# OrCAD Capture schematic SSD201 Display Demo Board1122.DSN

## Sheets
1 011.RMII: size B; title: SSD201 Display Demo Board; rev: r01; company: SigmaStar; note: RMII
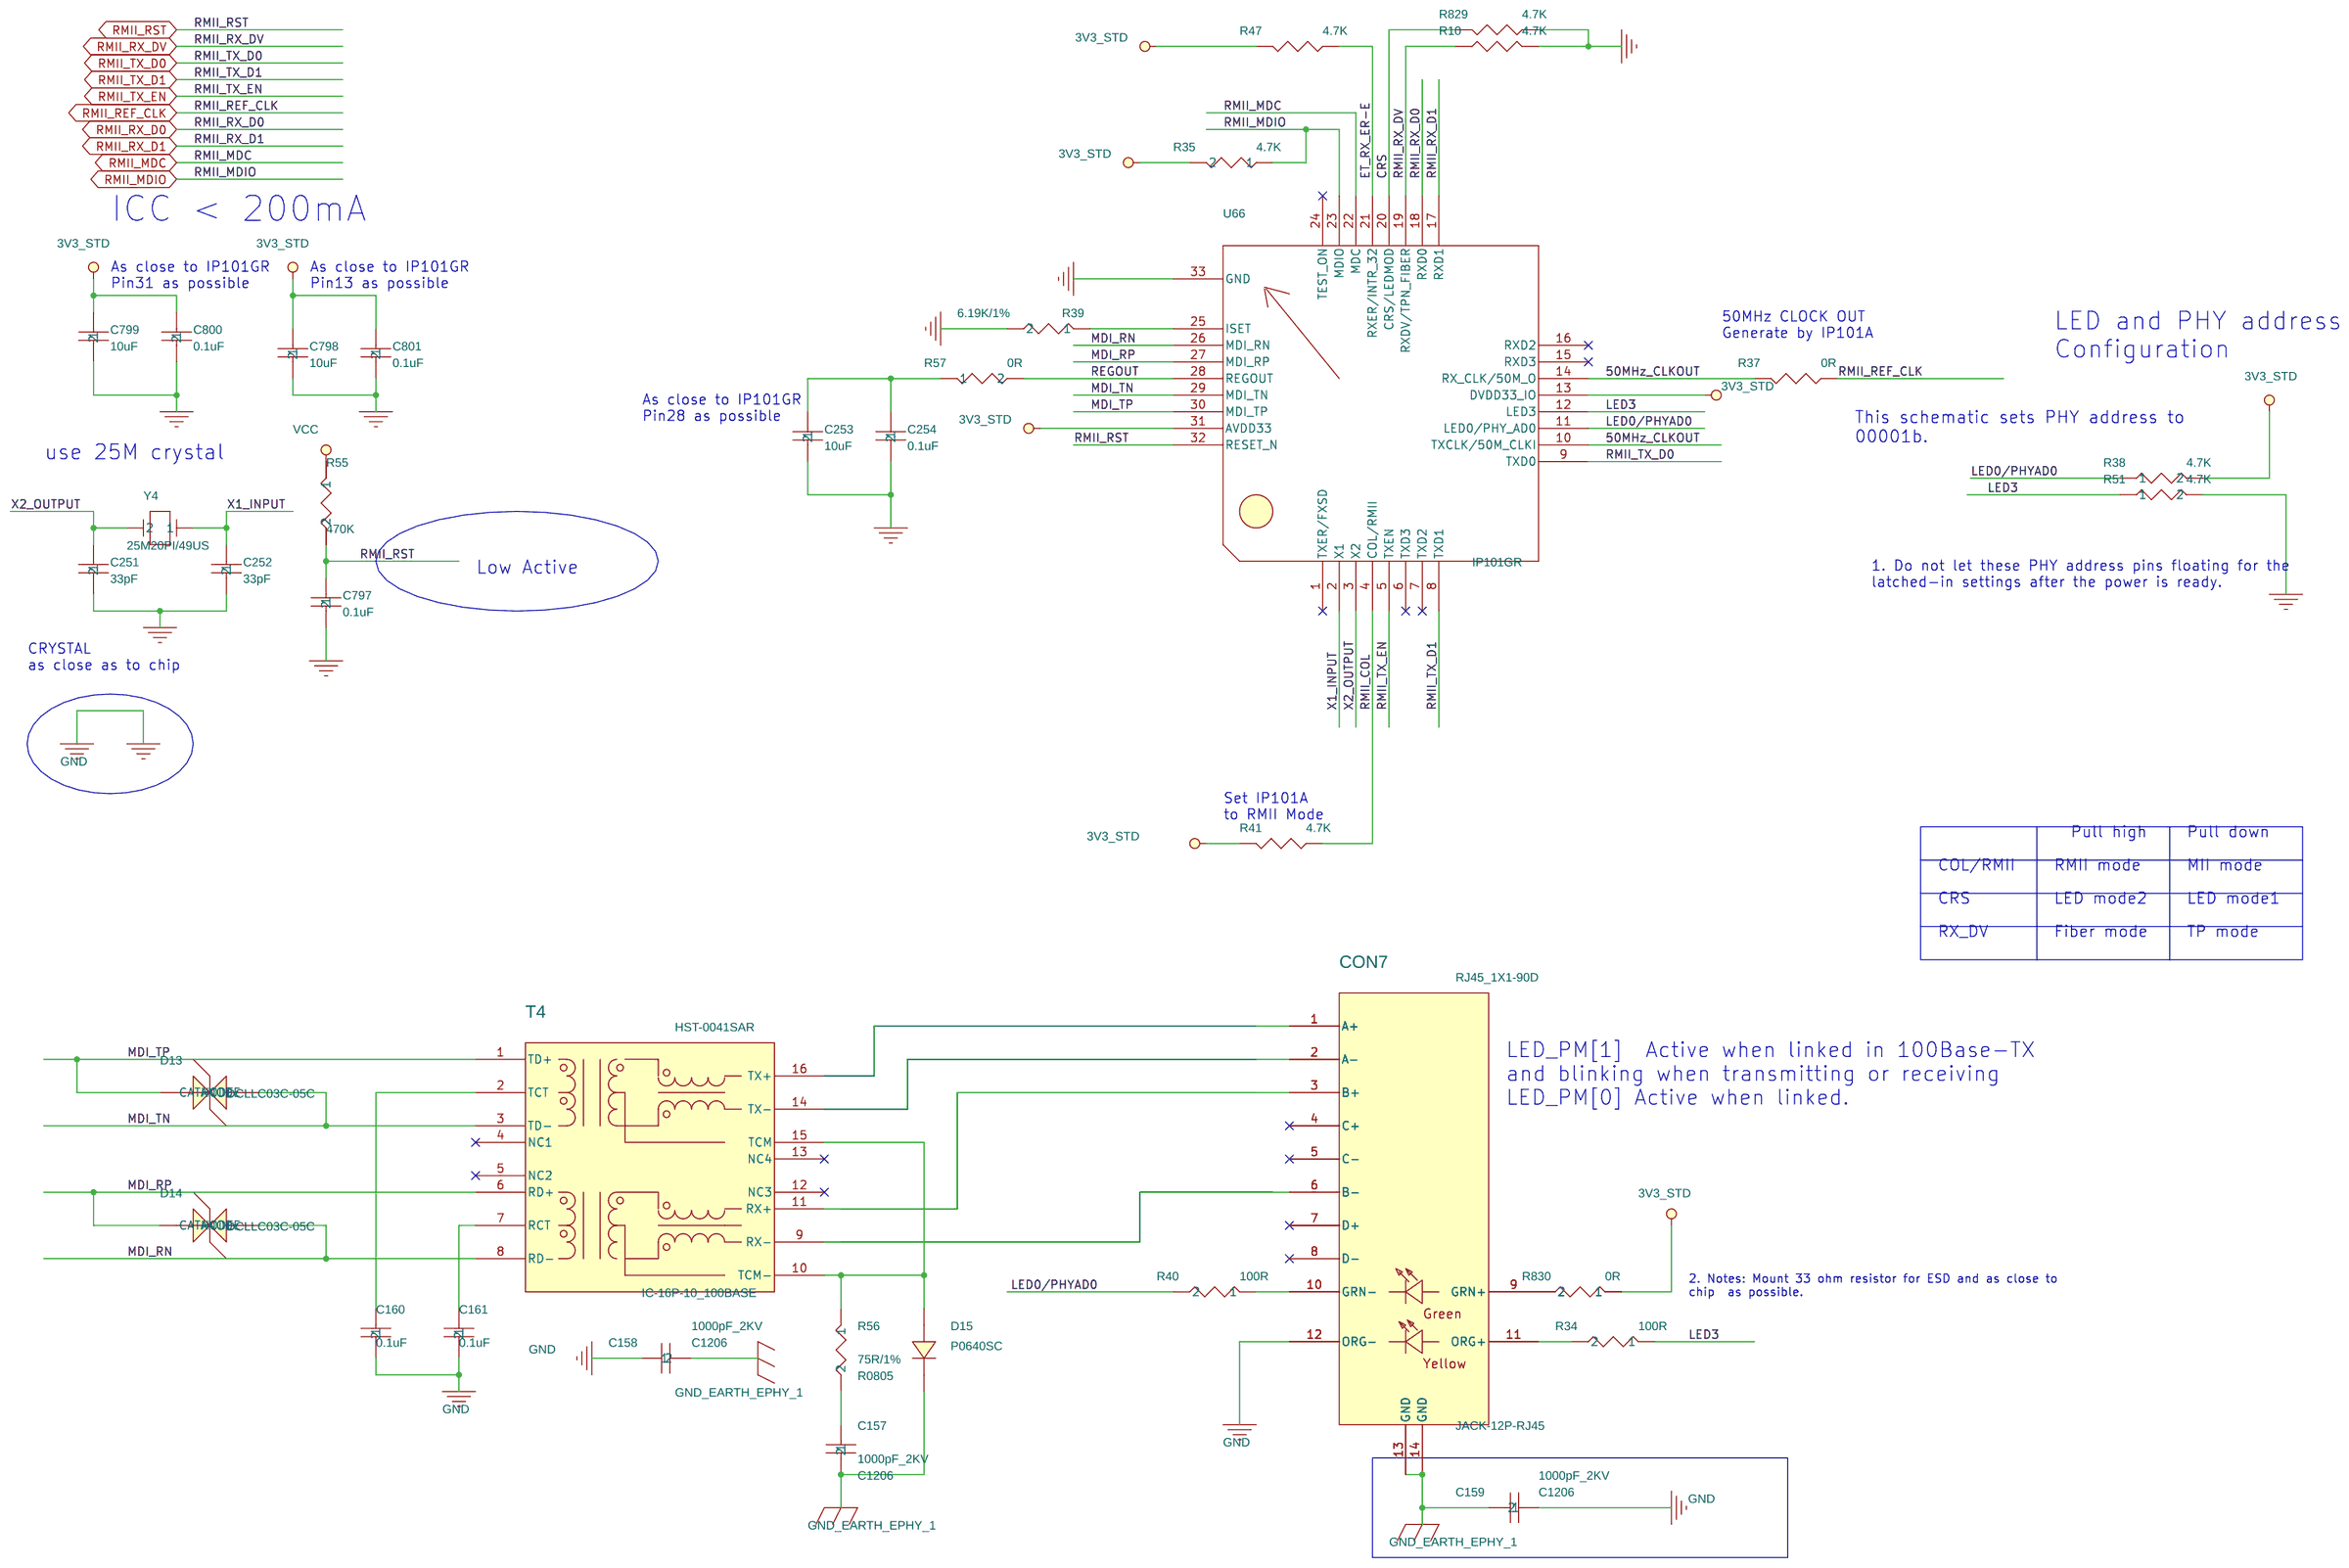
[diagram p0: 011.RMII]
2 001. Revision: rev: r0.1; note: Revision History
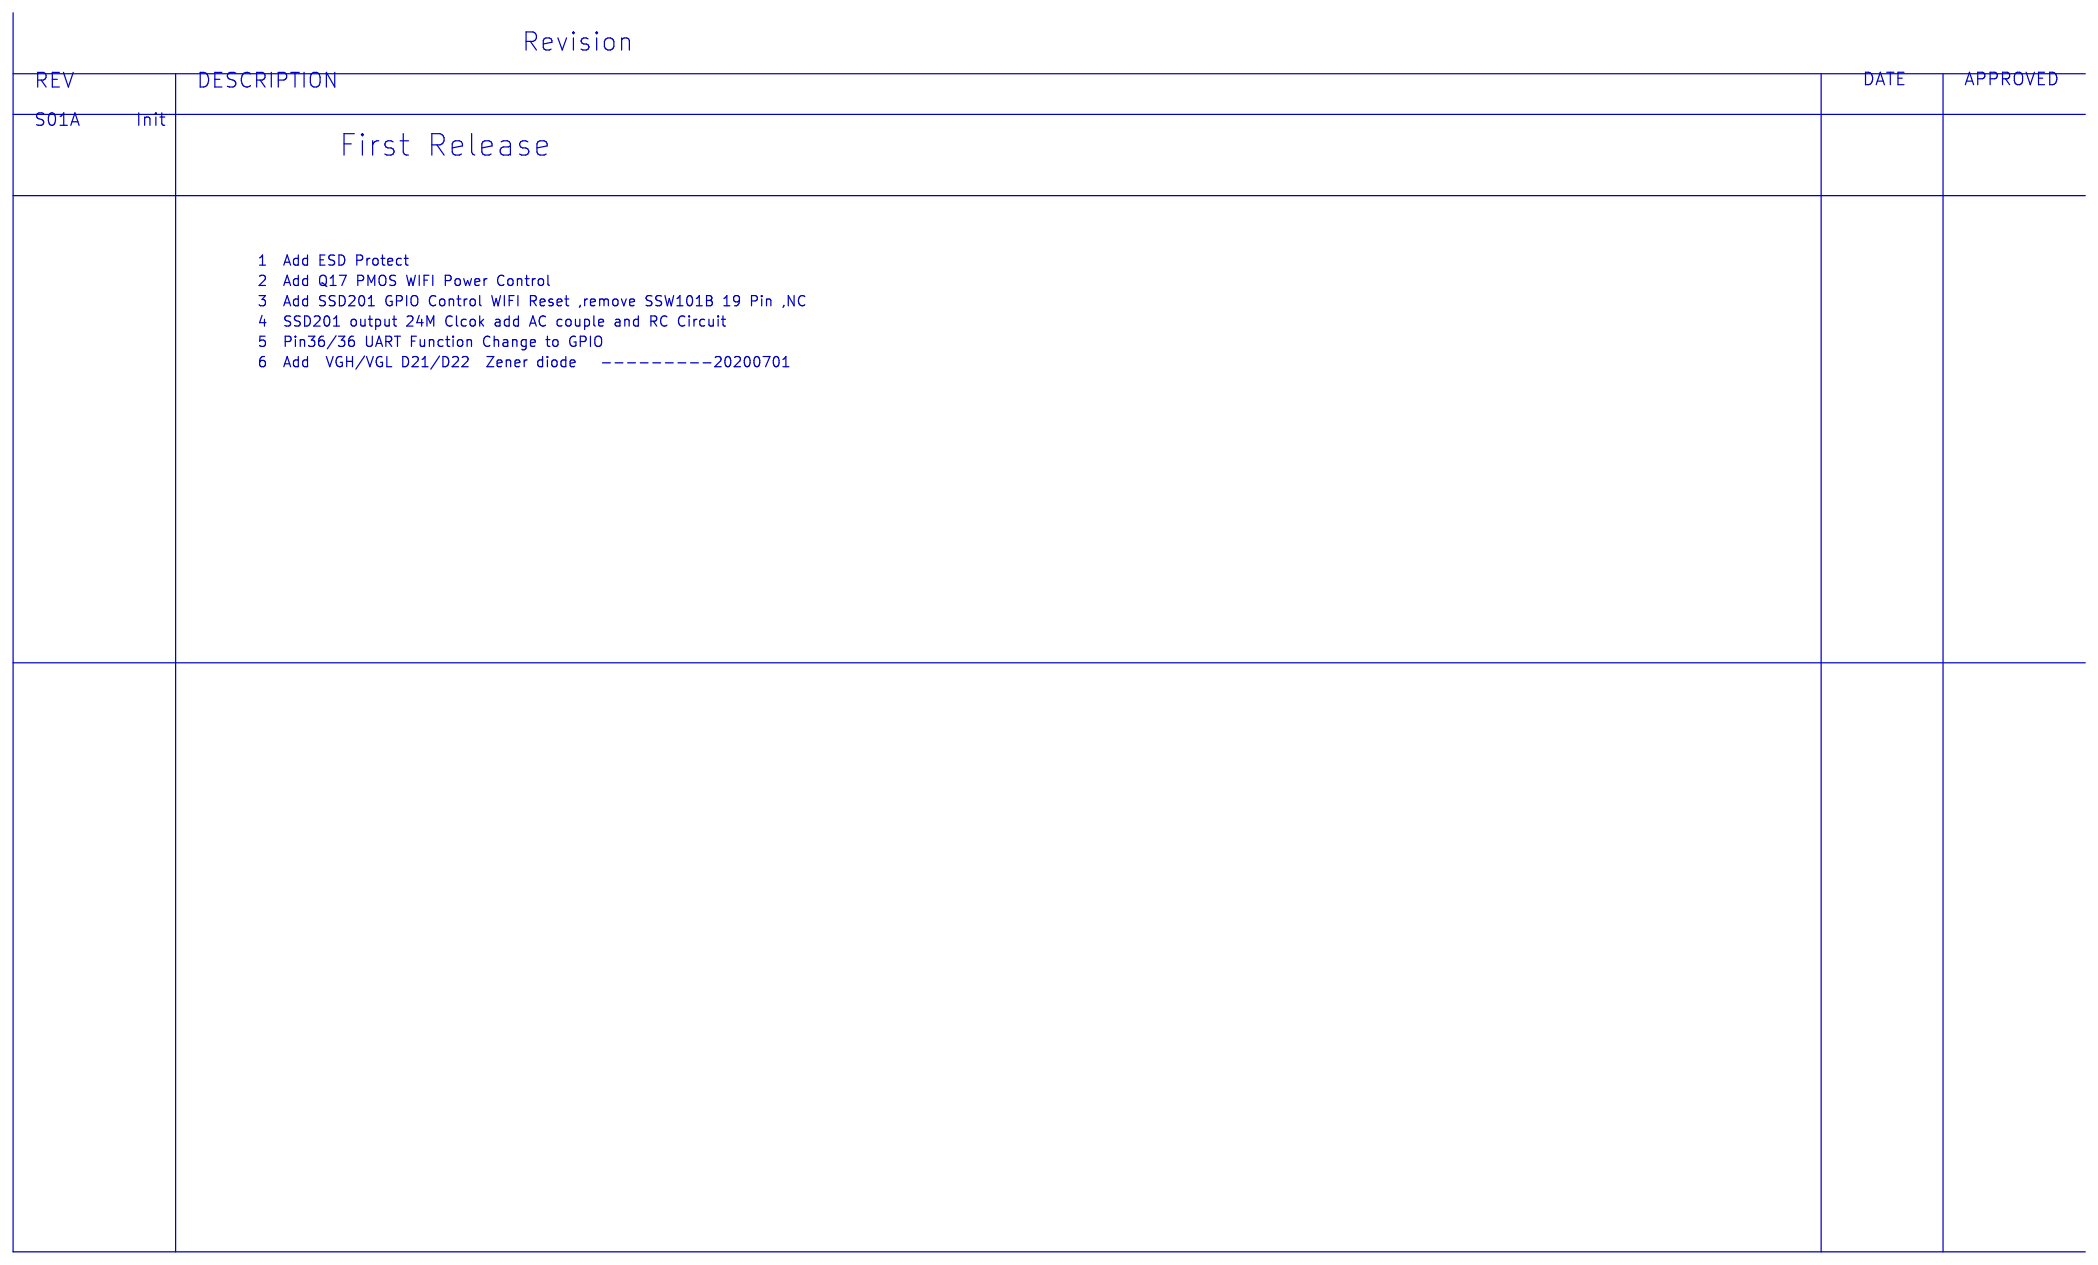
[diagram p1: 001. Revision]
3 002. Block Diagrom: rev: r0.1; note: Block Diagram
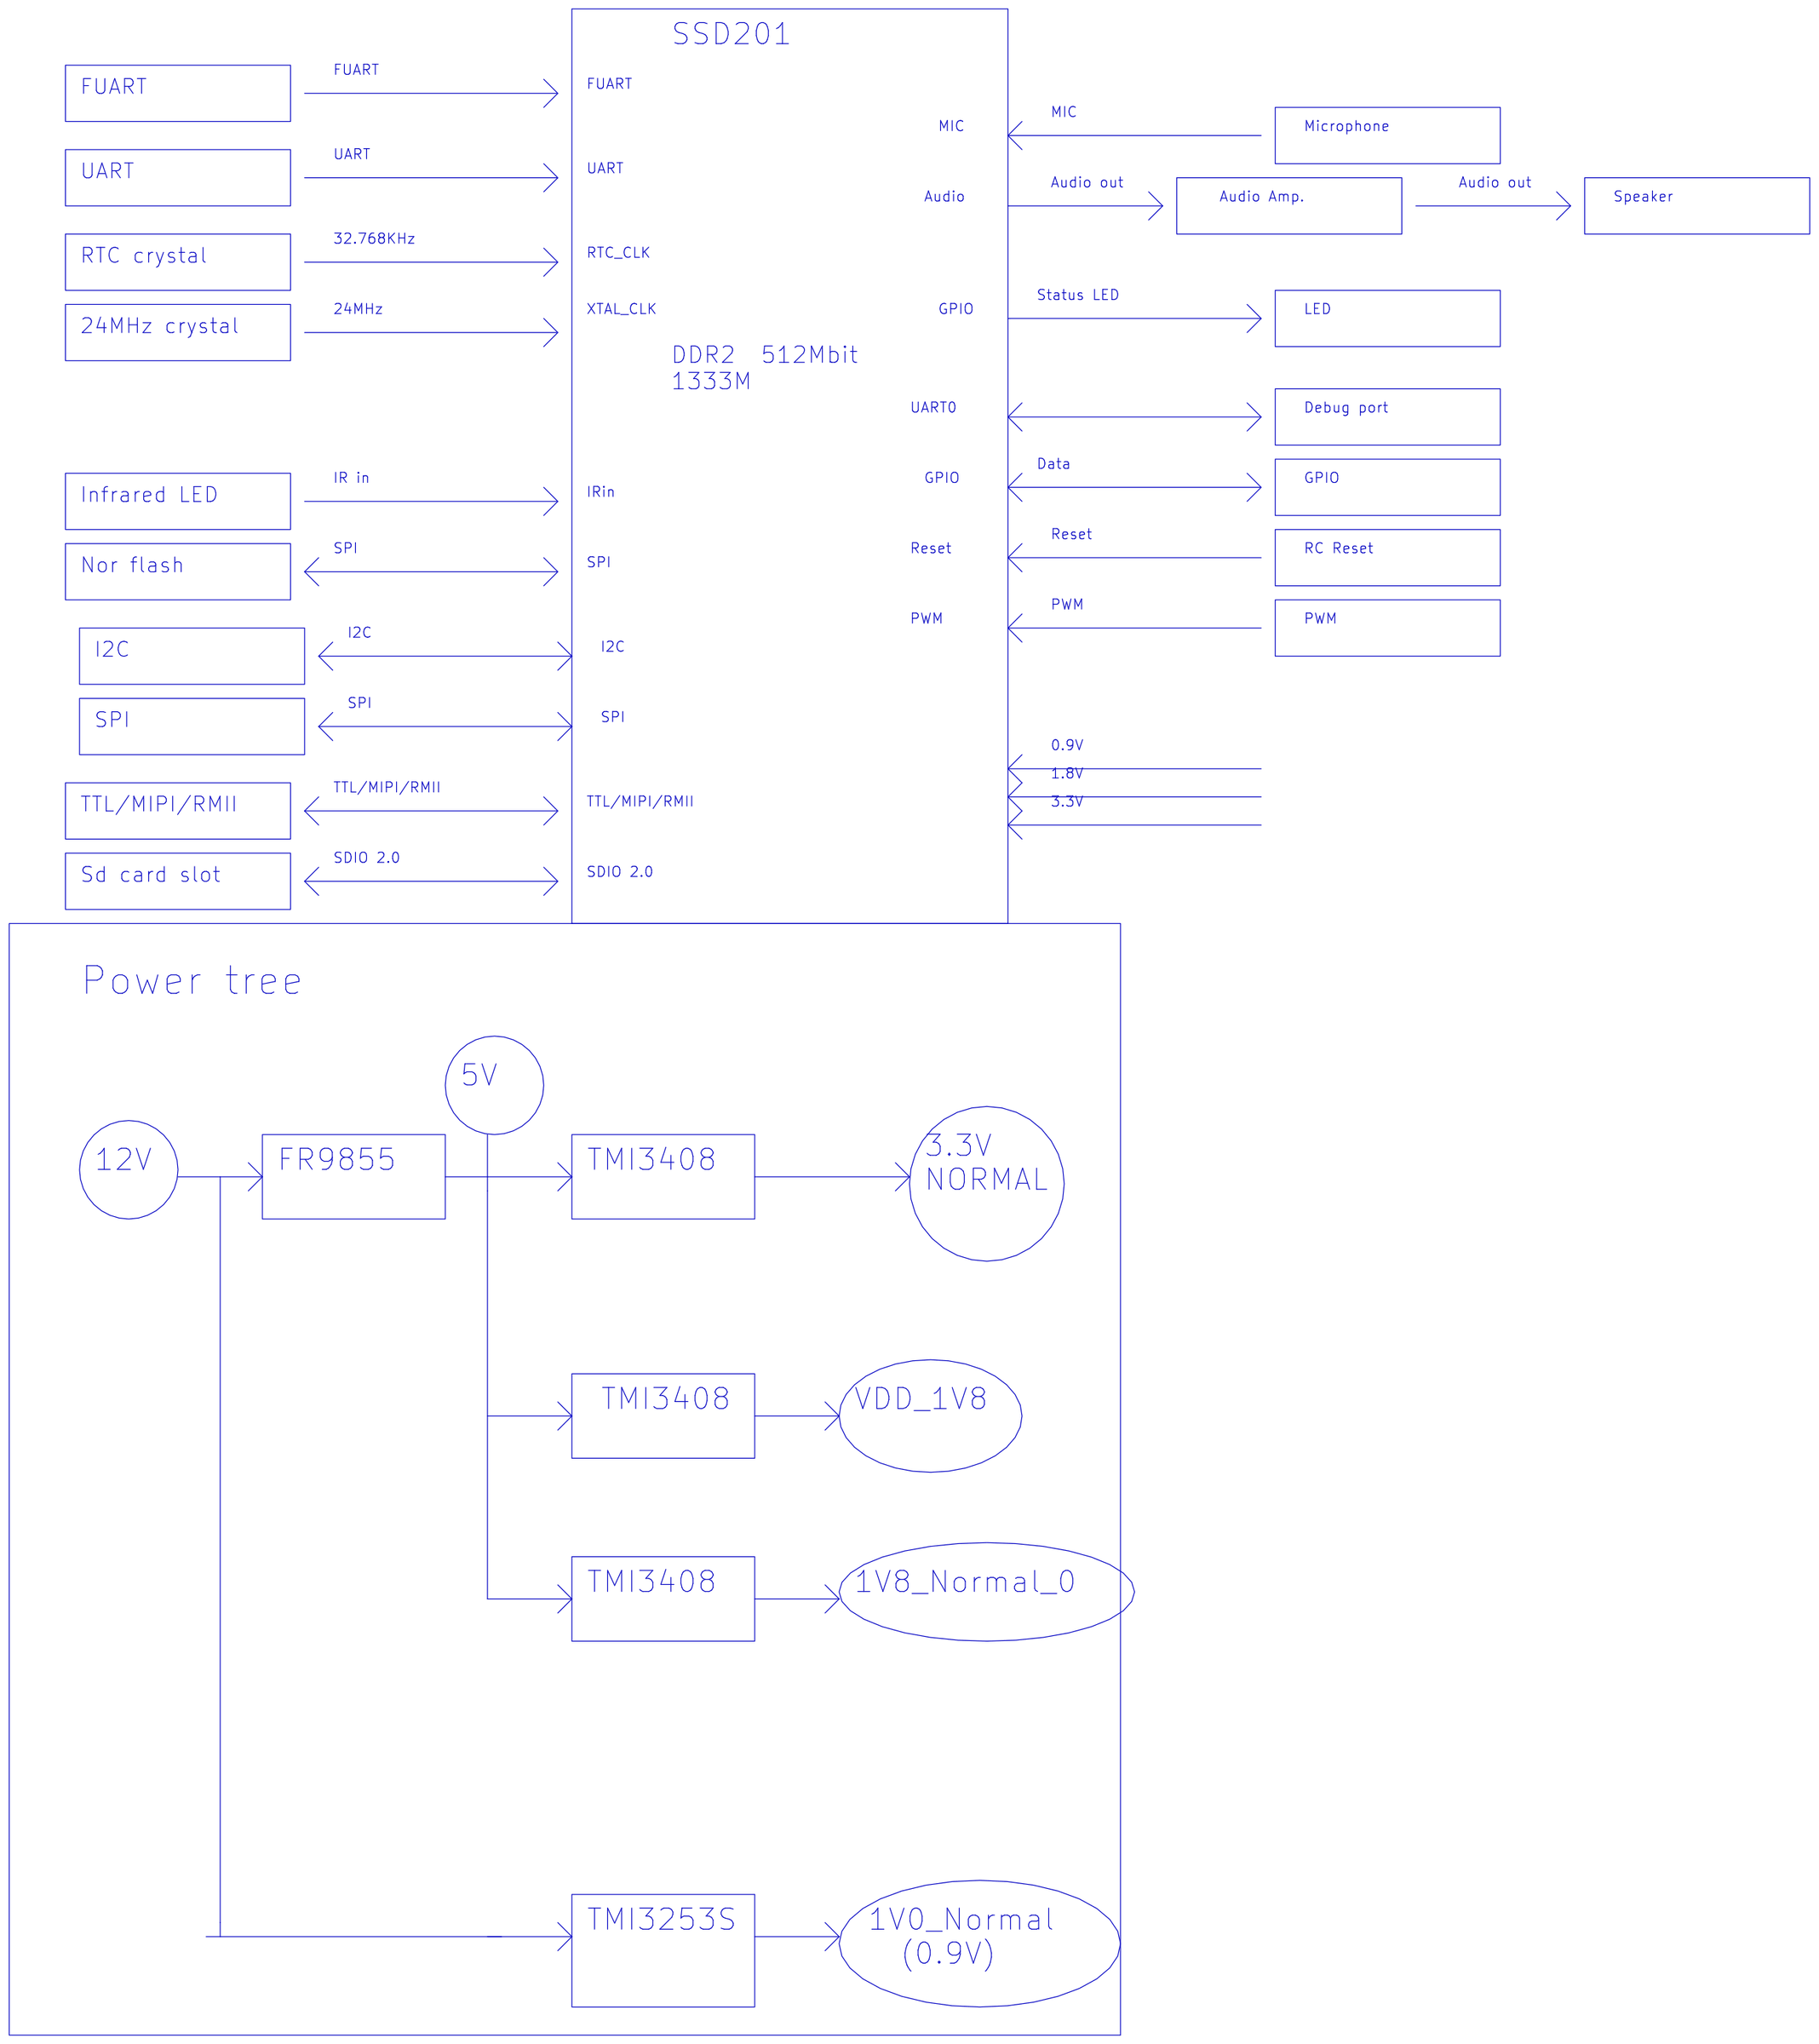
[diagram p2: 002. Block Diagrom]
4 003. Power: size C; rev: r0.1; note: Power
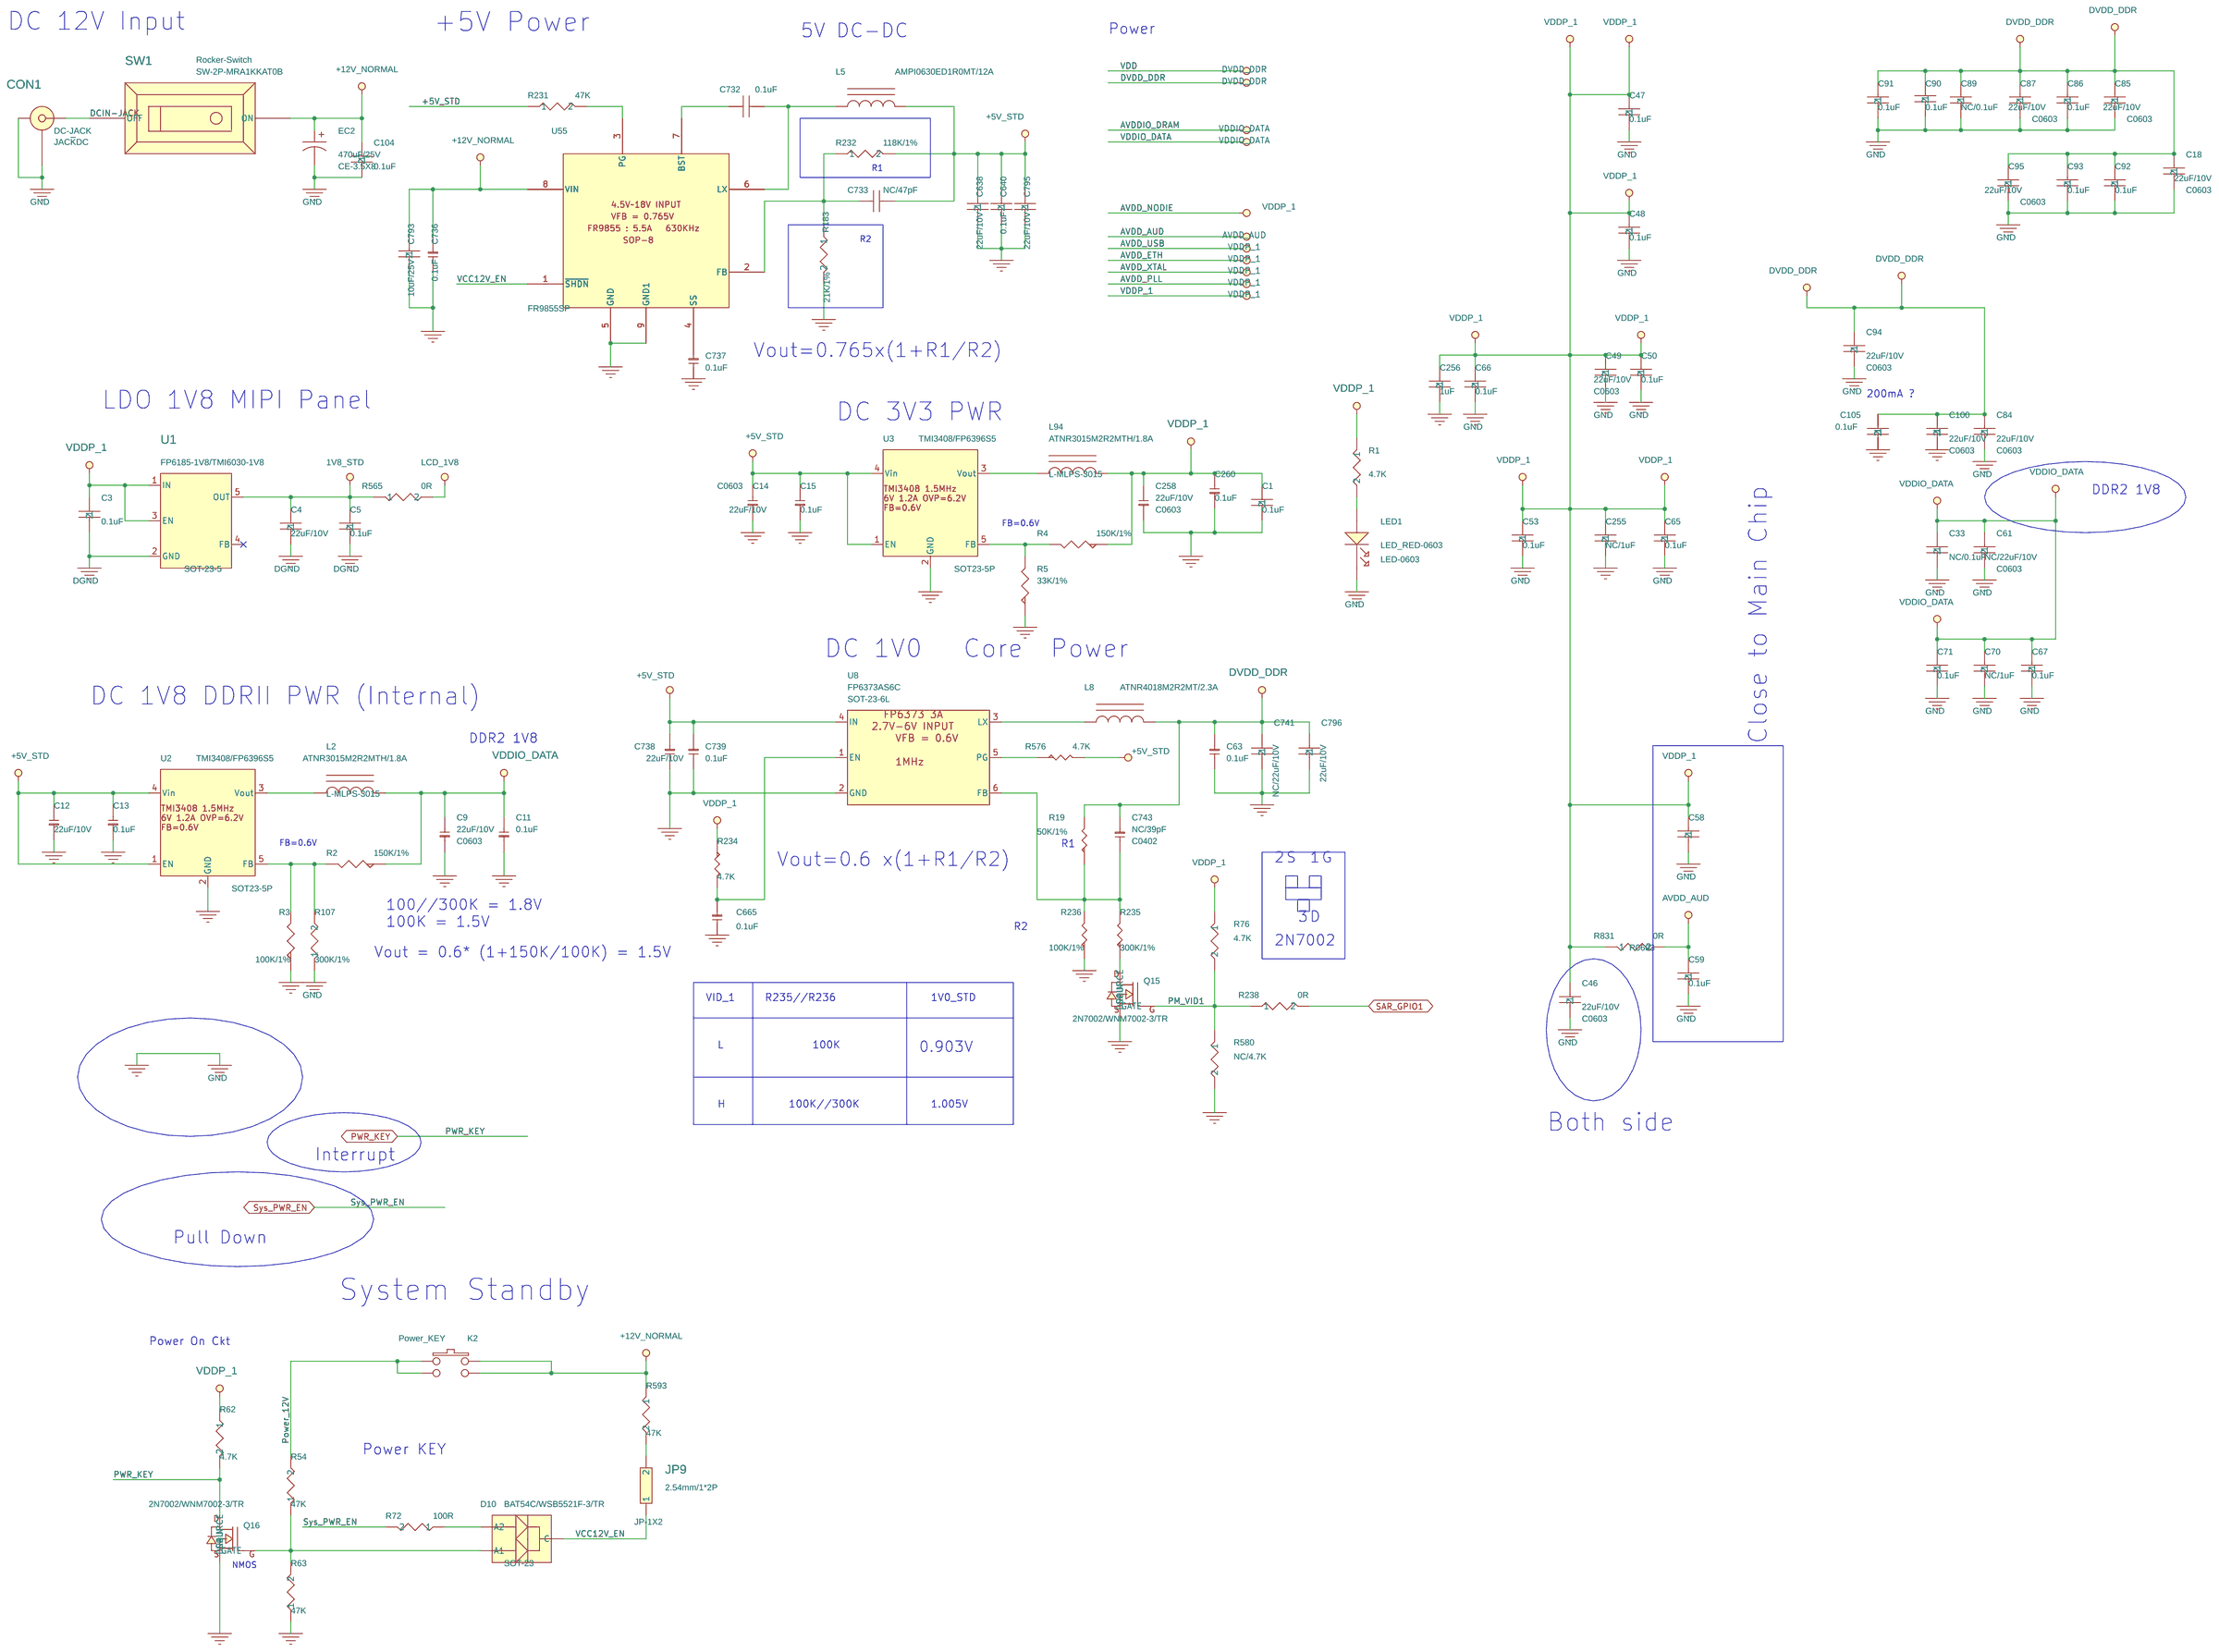
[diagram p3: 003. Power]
5 004. SSD201: size C; rev: r0.1; note: SOC_ SPI Flash / JTAG / IR / eFuse
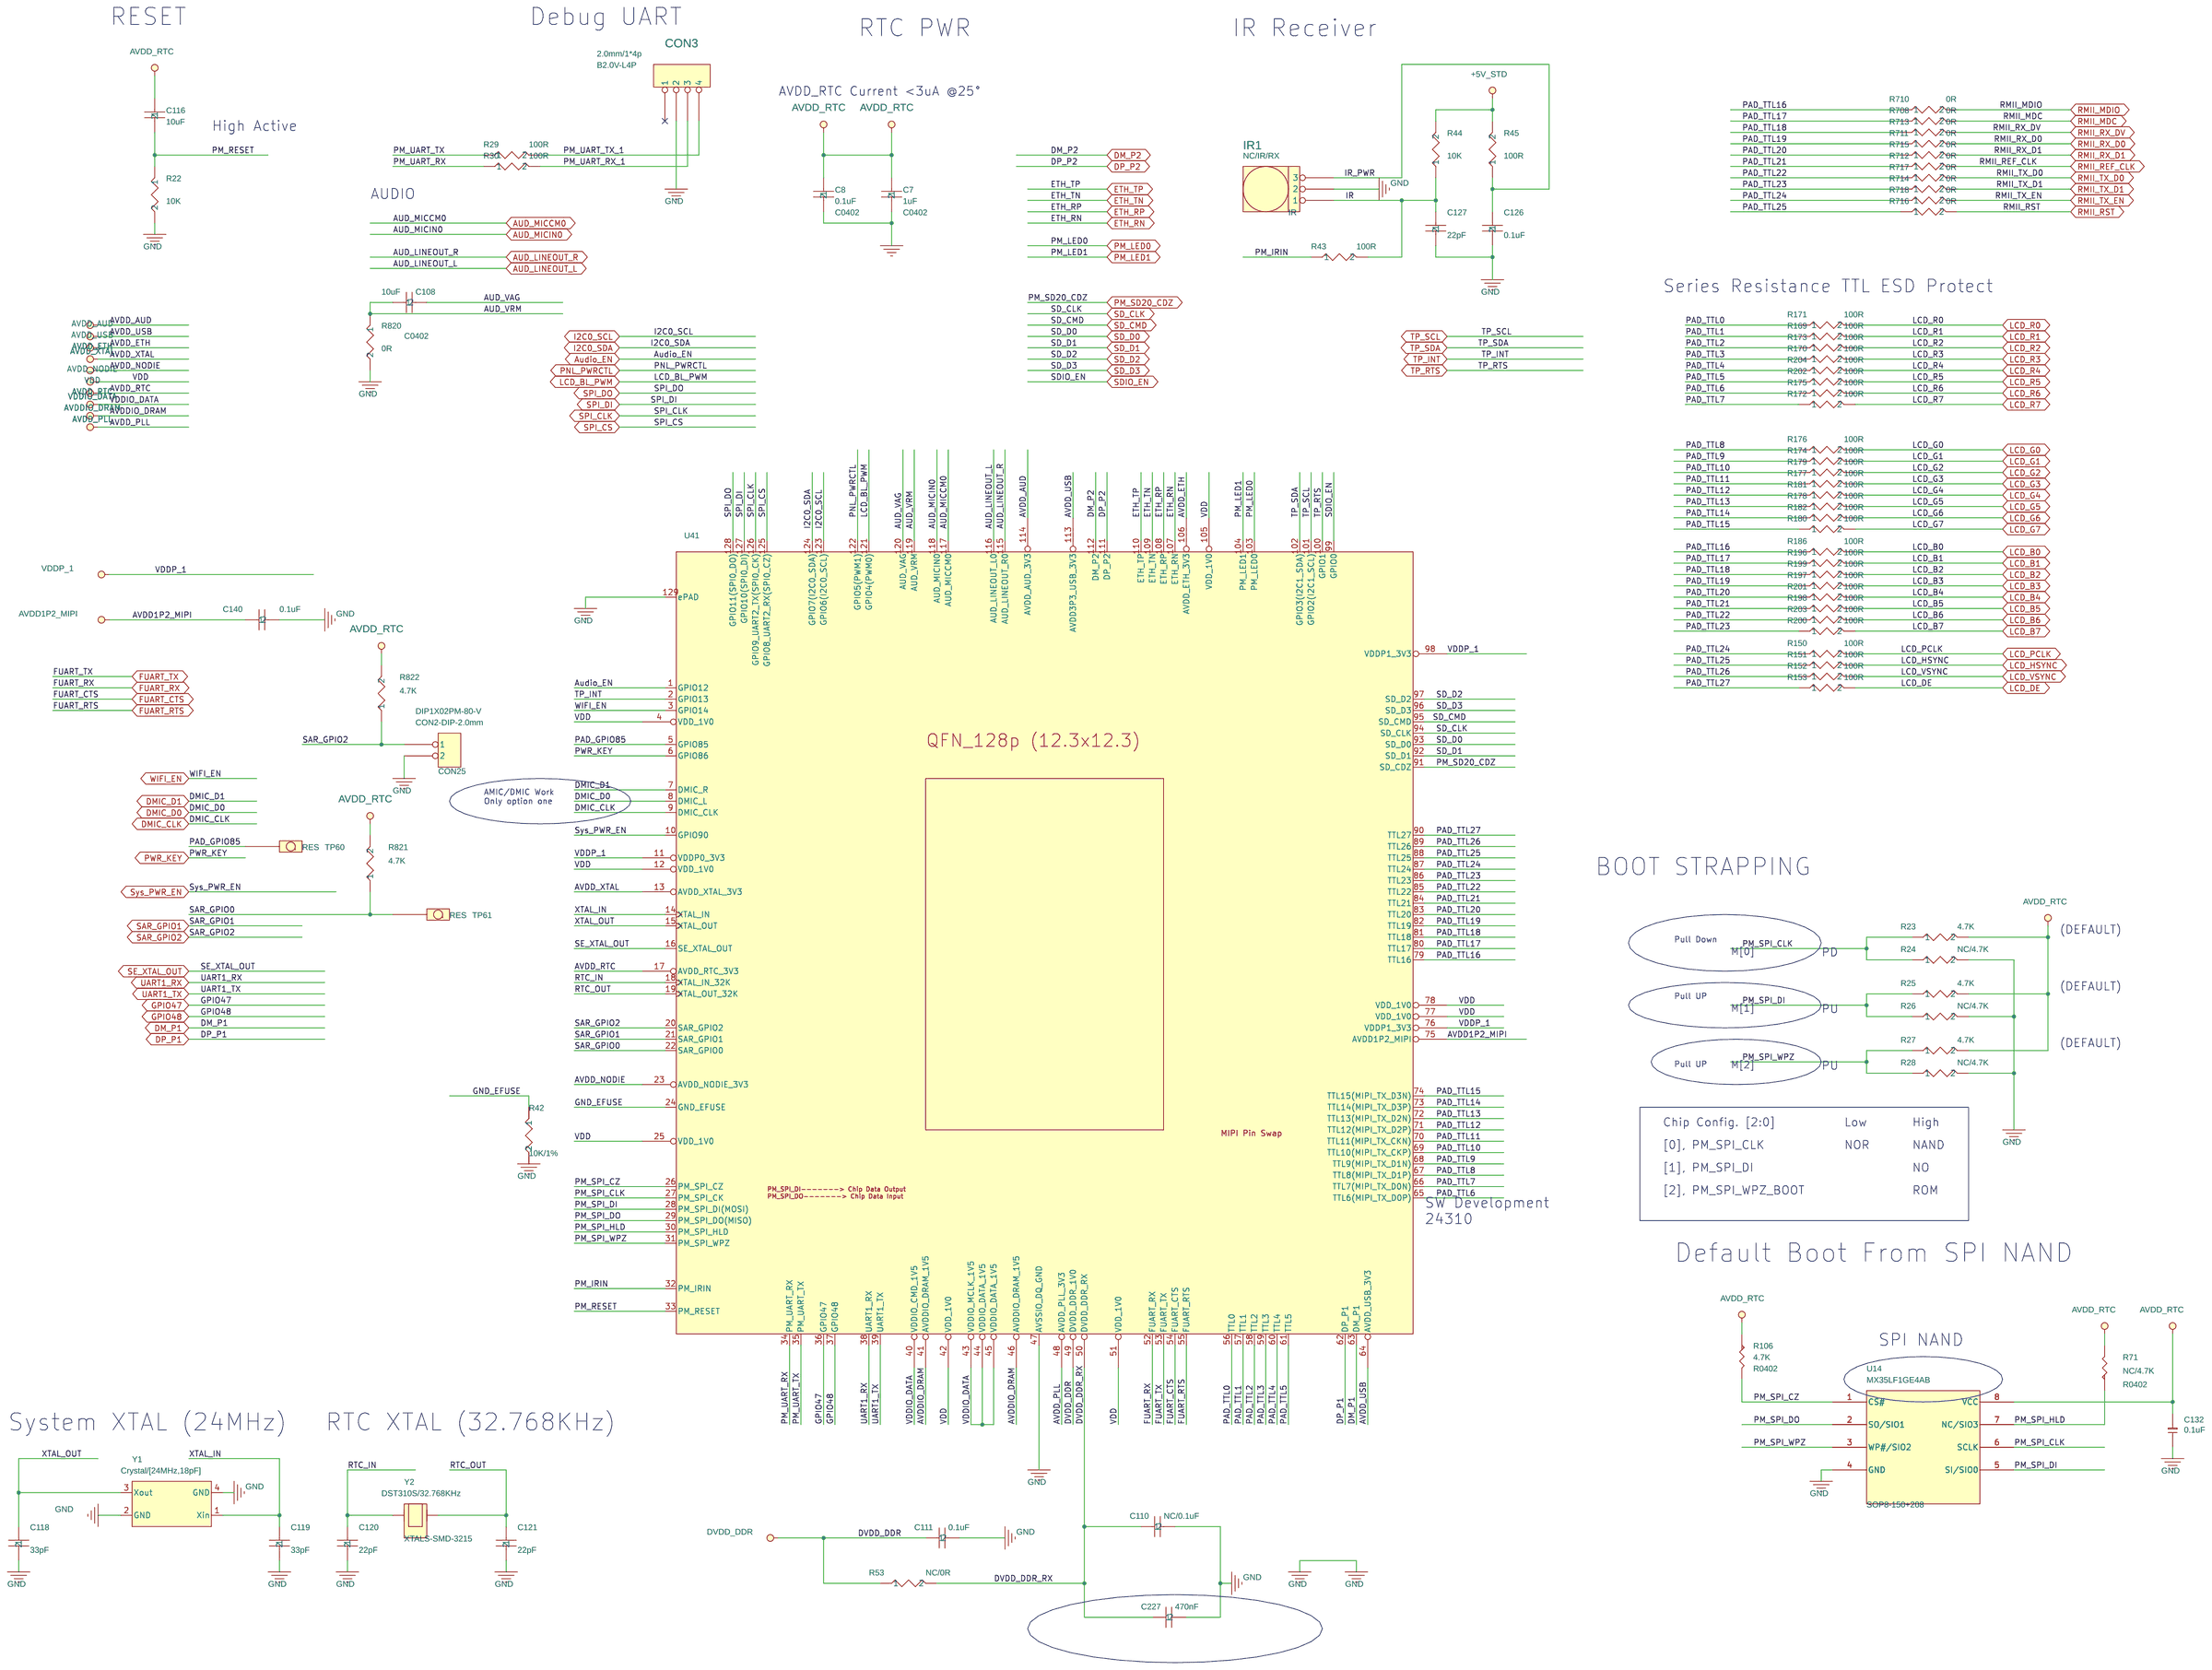
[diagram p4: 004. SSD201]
6 008. Audio: size A; note: Audio
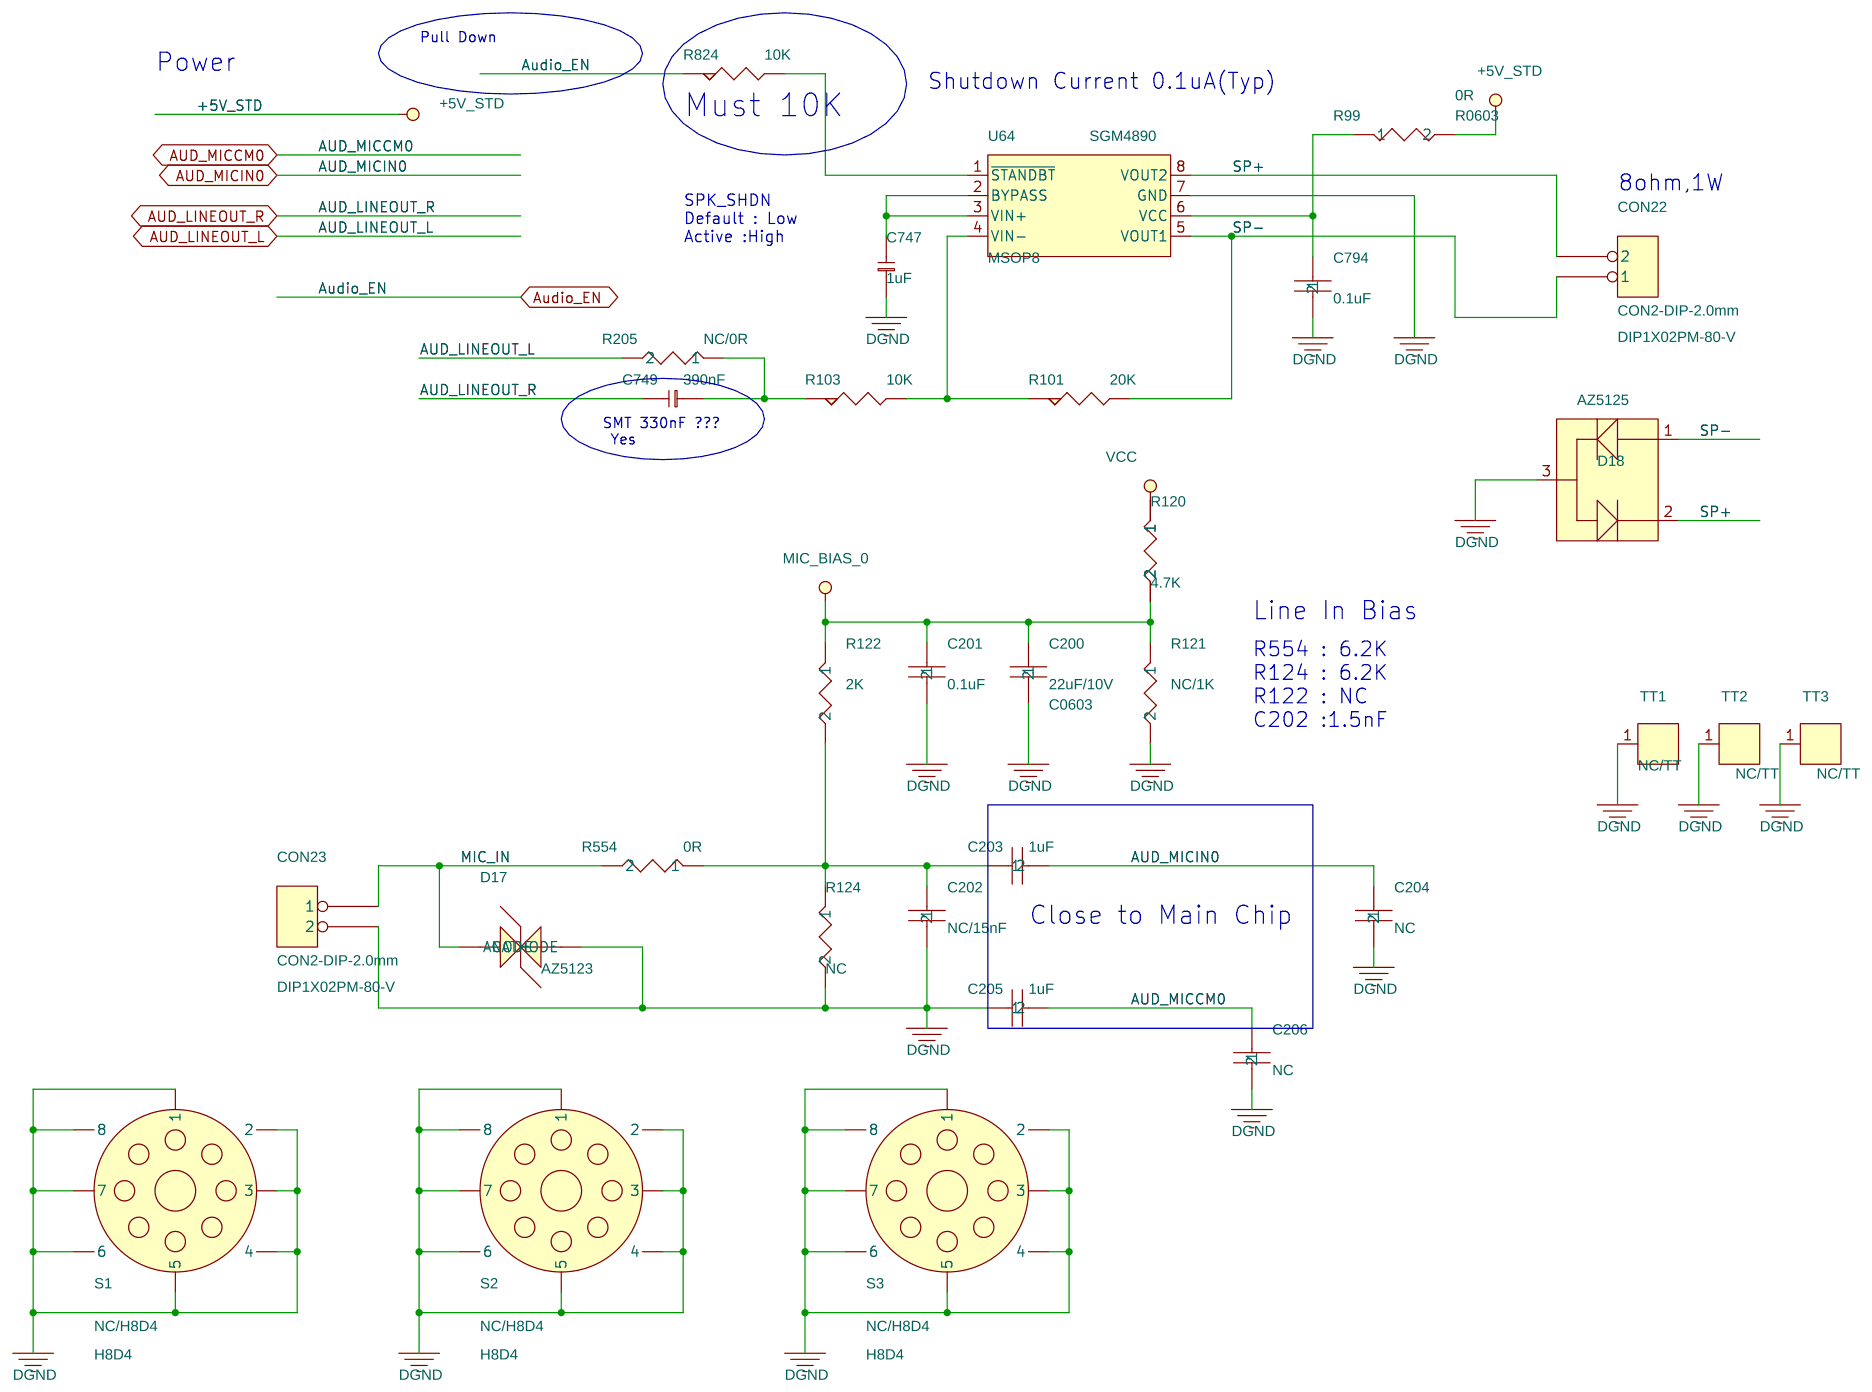
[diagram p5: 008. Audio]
7 009.TTL Panel: size B; note: Display-TTL Panel
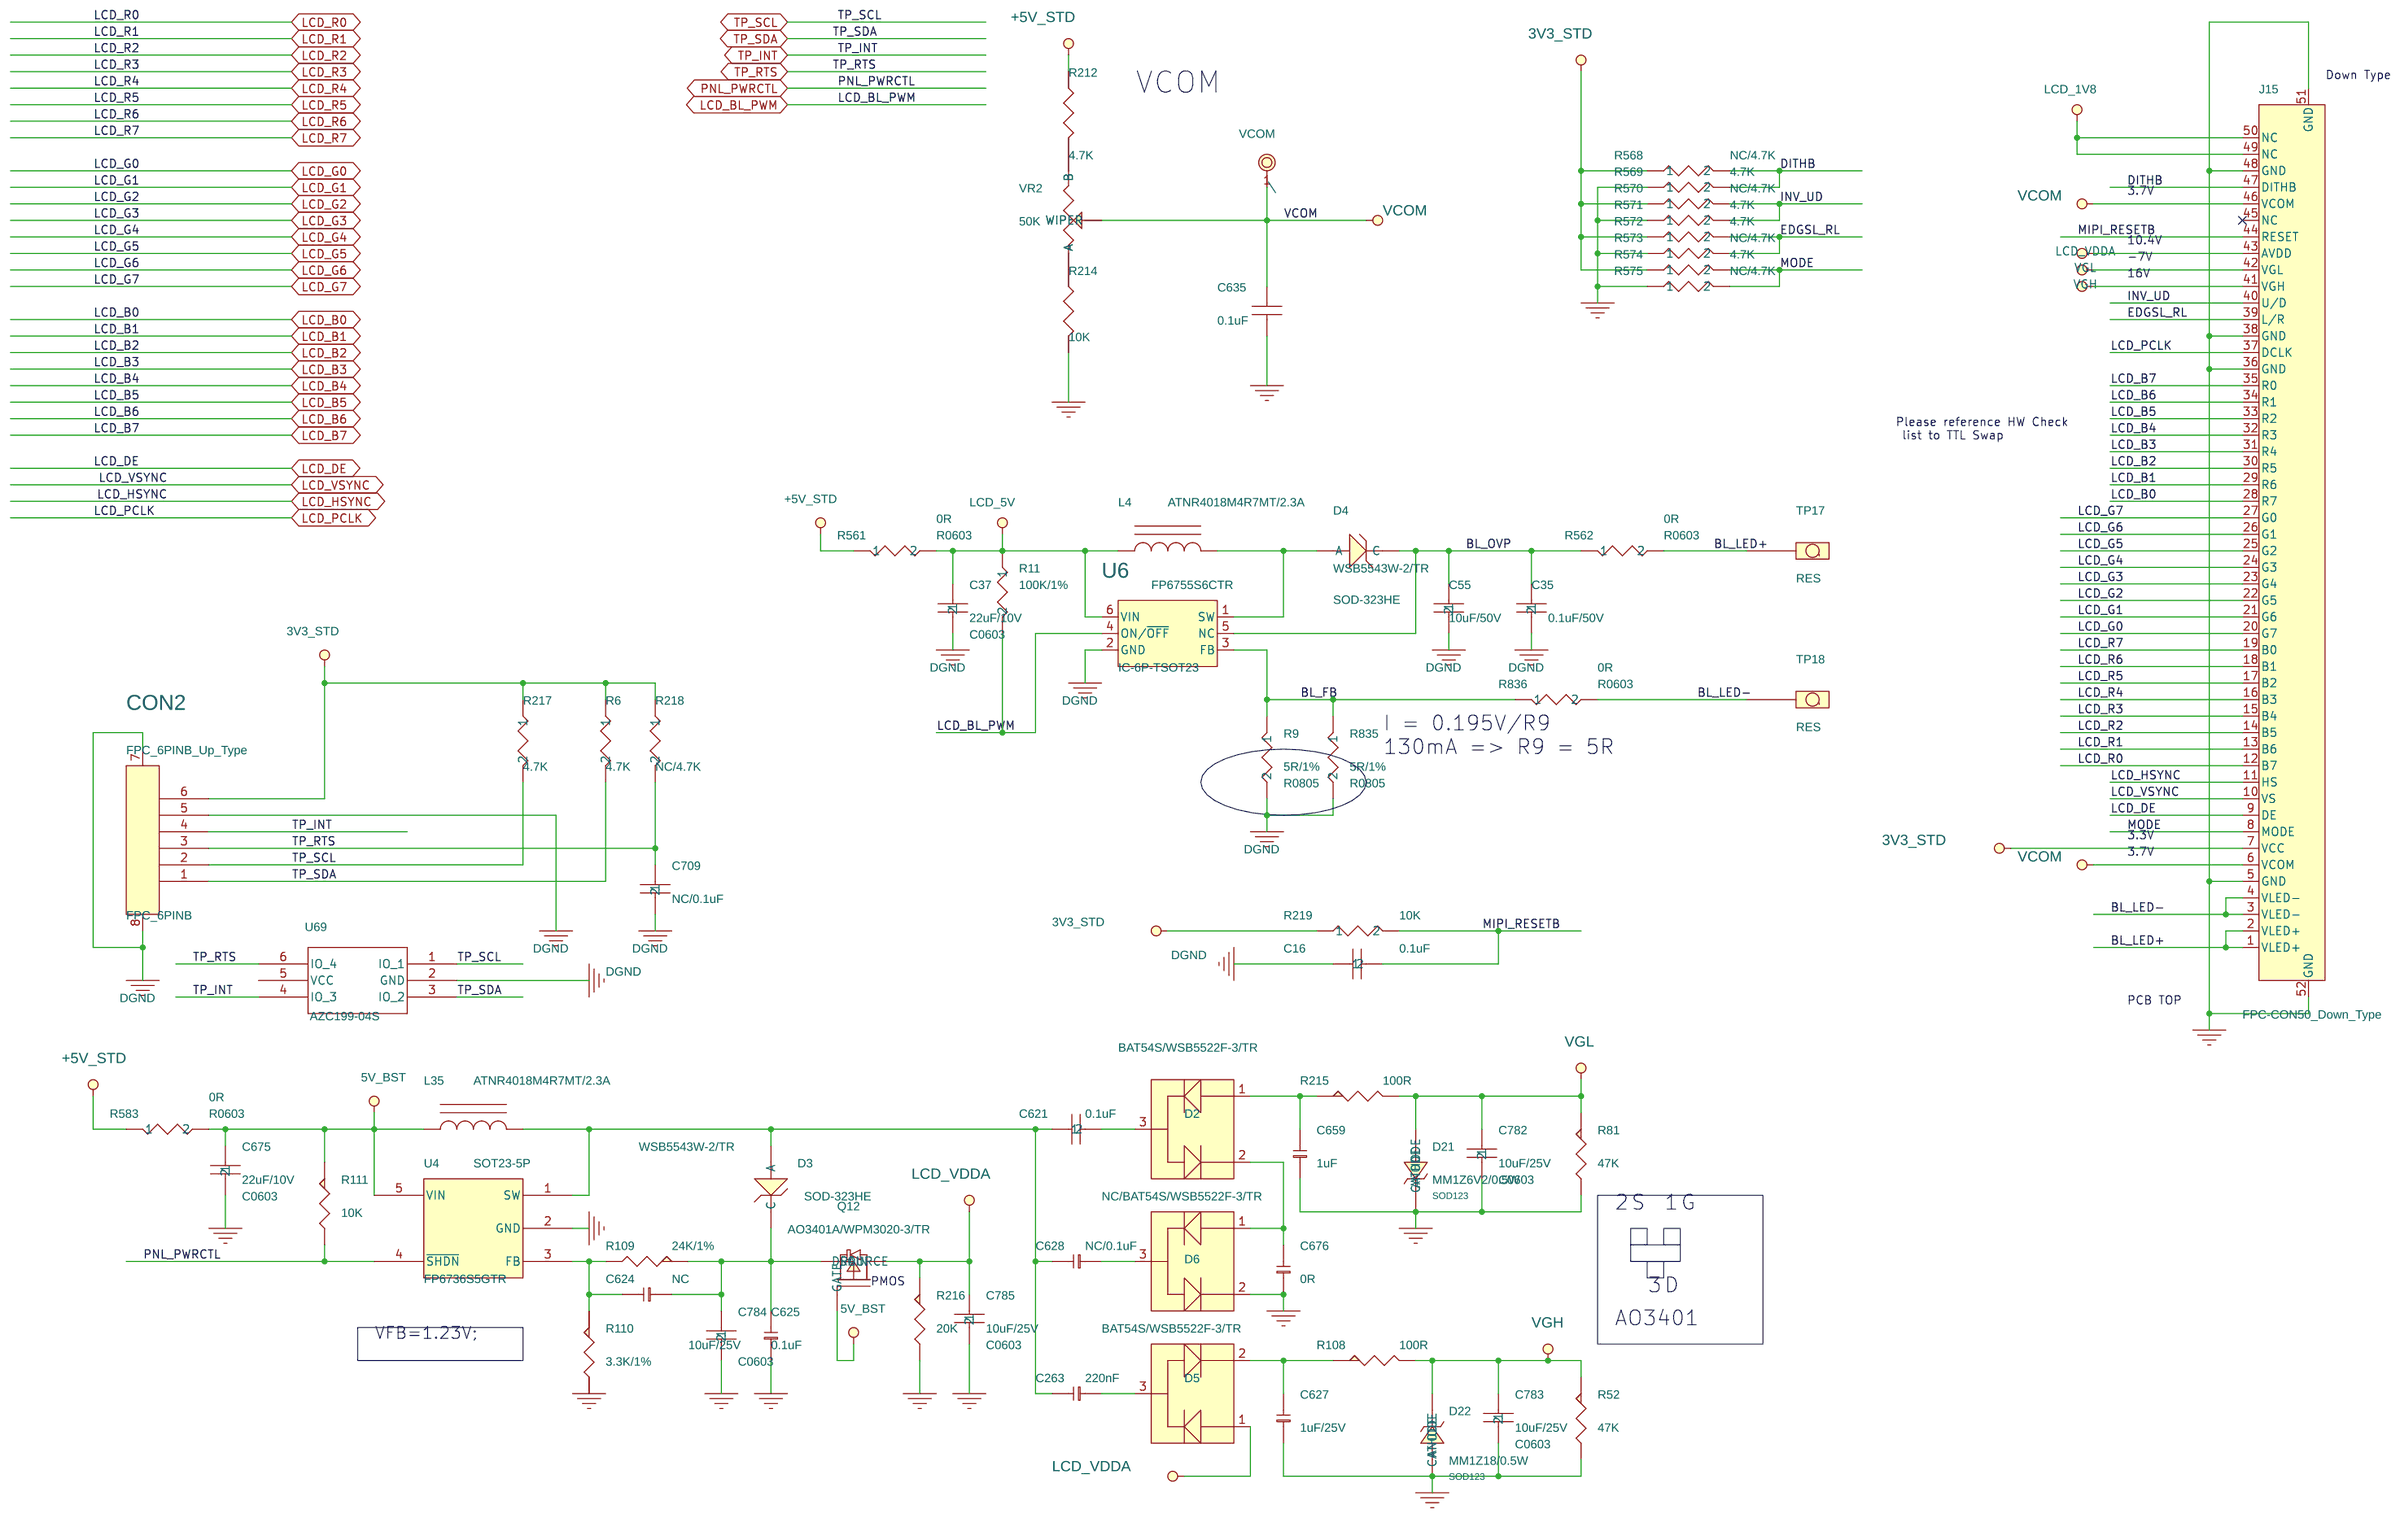
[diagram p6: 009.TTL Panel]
8 010.USB_WIFI: size B; note: USB WIFI
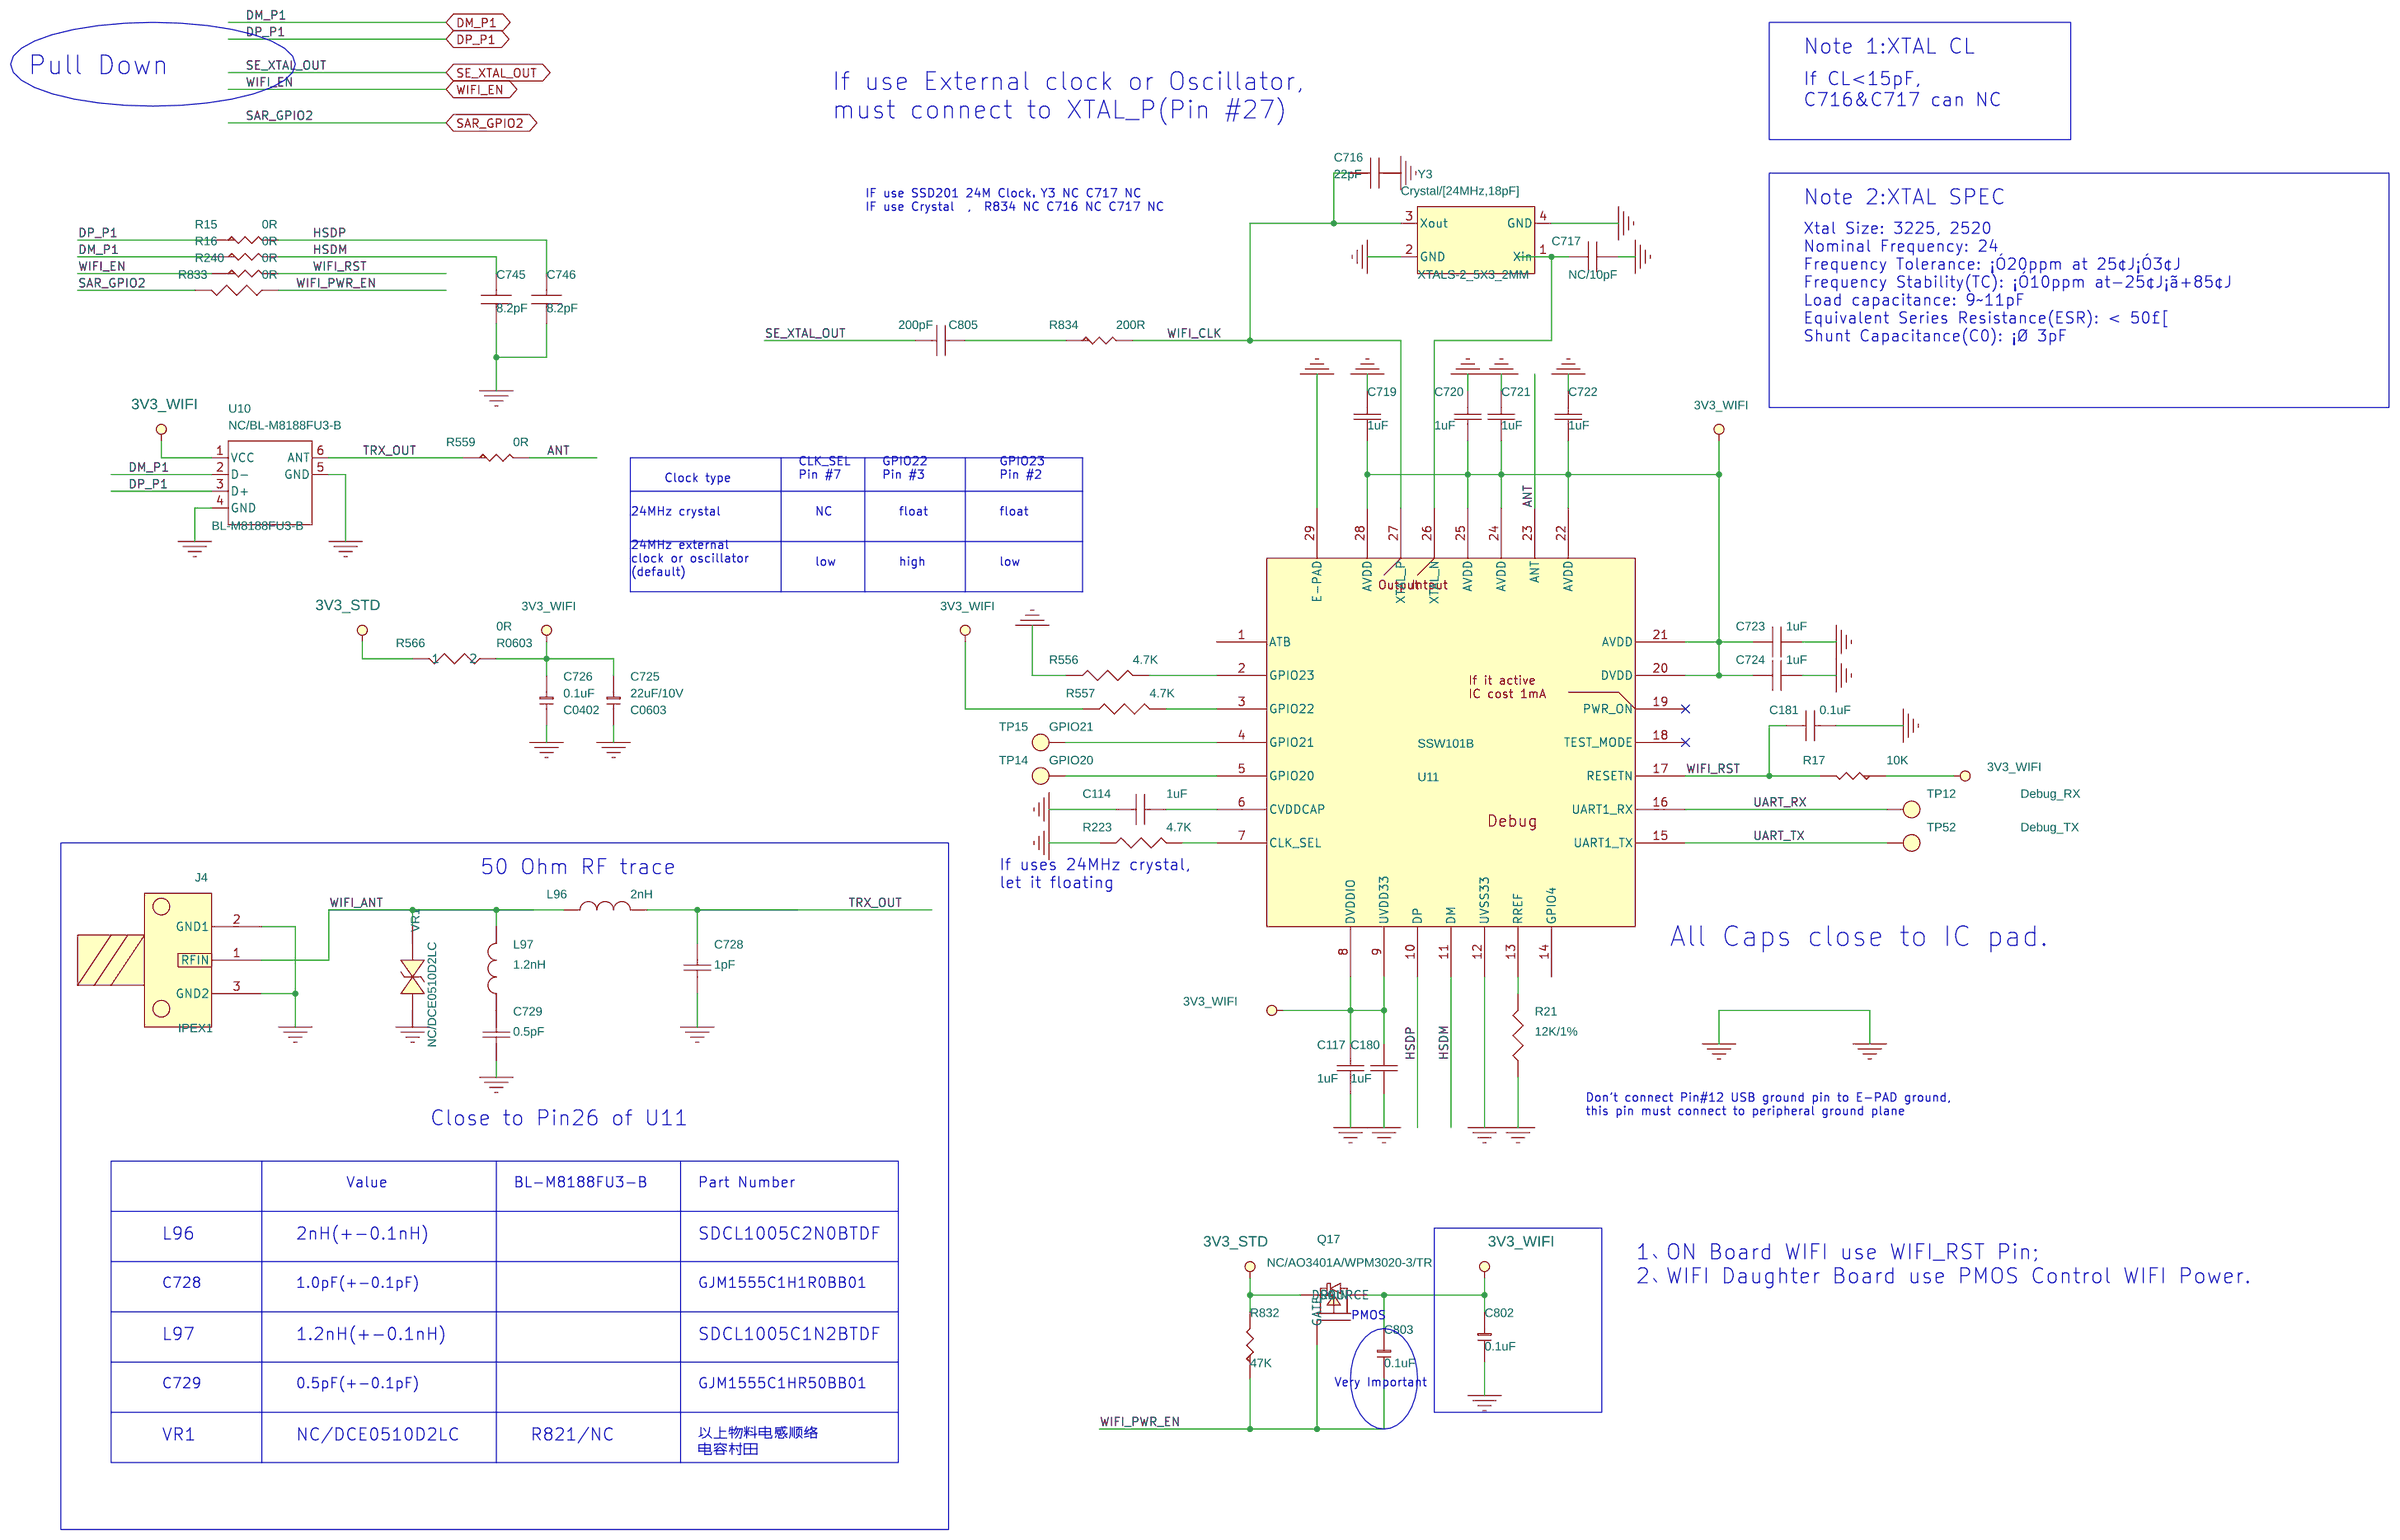
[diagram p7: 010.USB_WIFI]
9 007.SD/SDIO: size A; note: SD
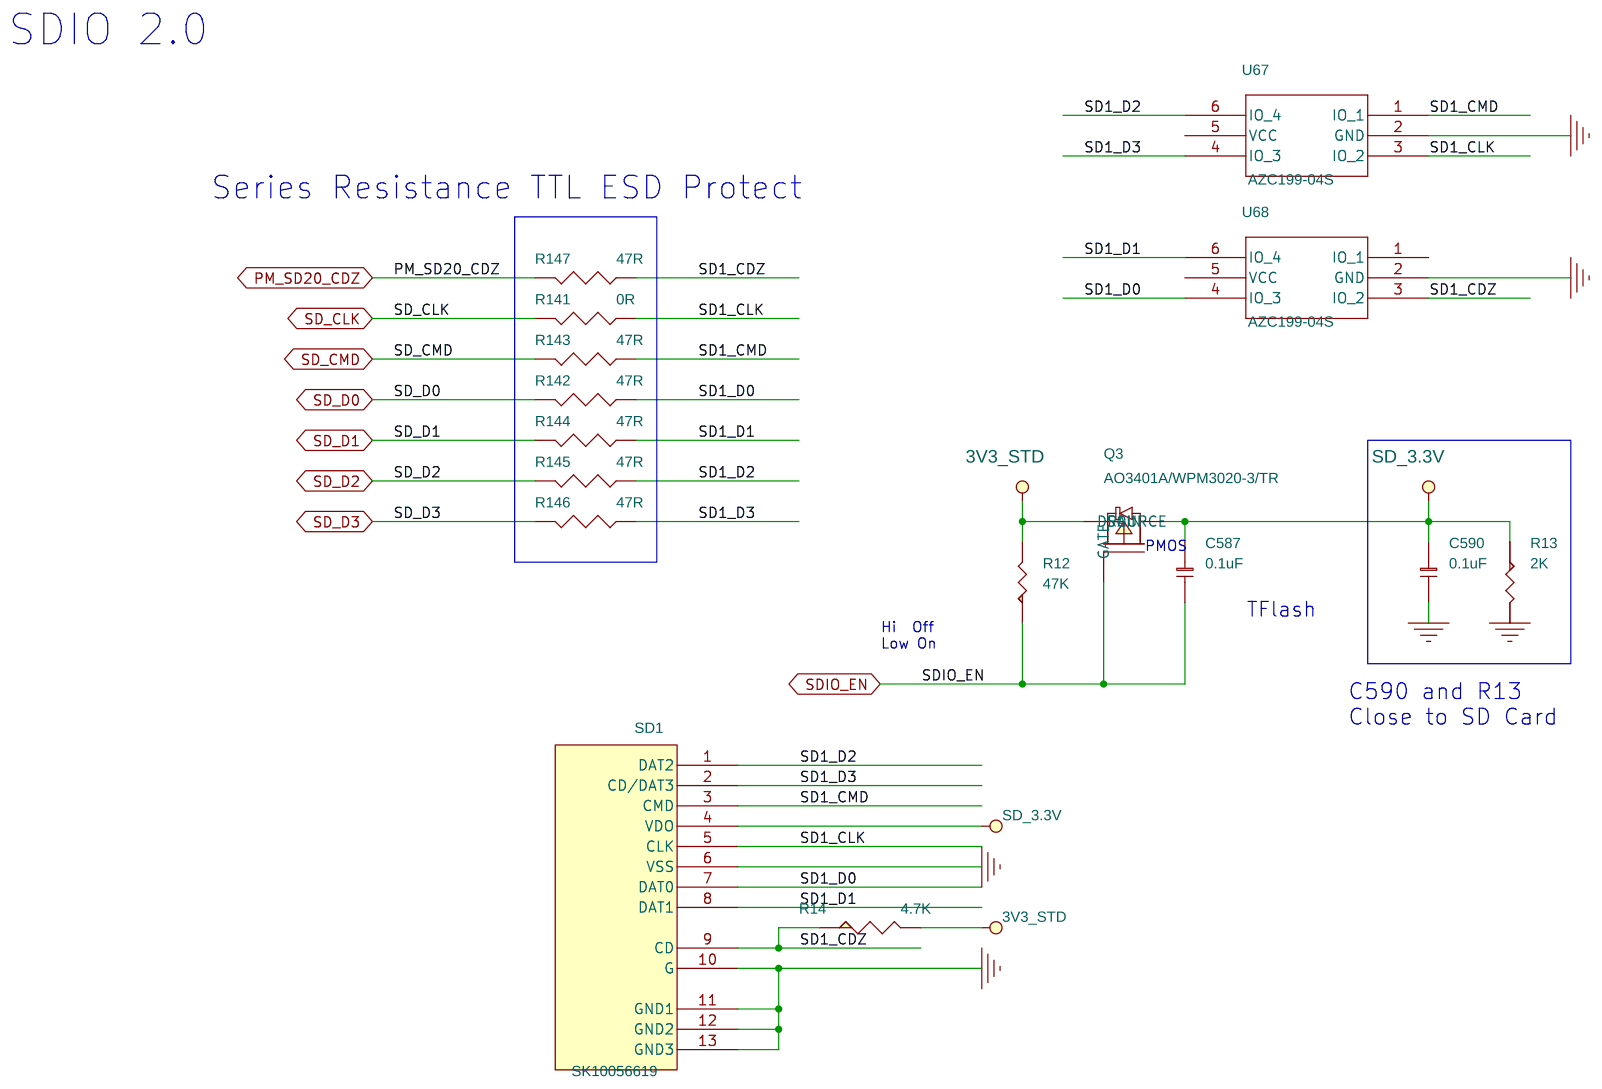
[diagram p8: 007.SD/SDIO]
10 006. USB/ePHY: size B; note: USB
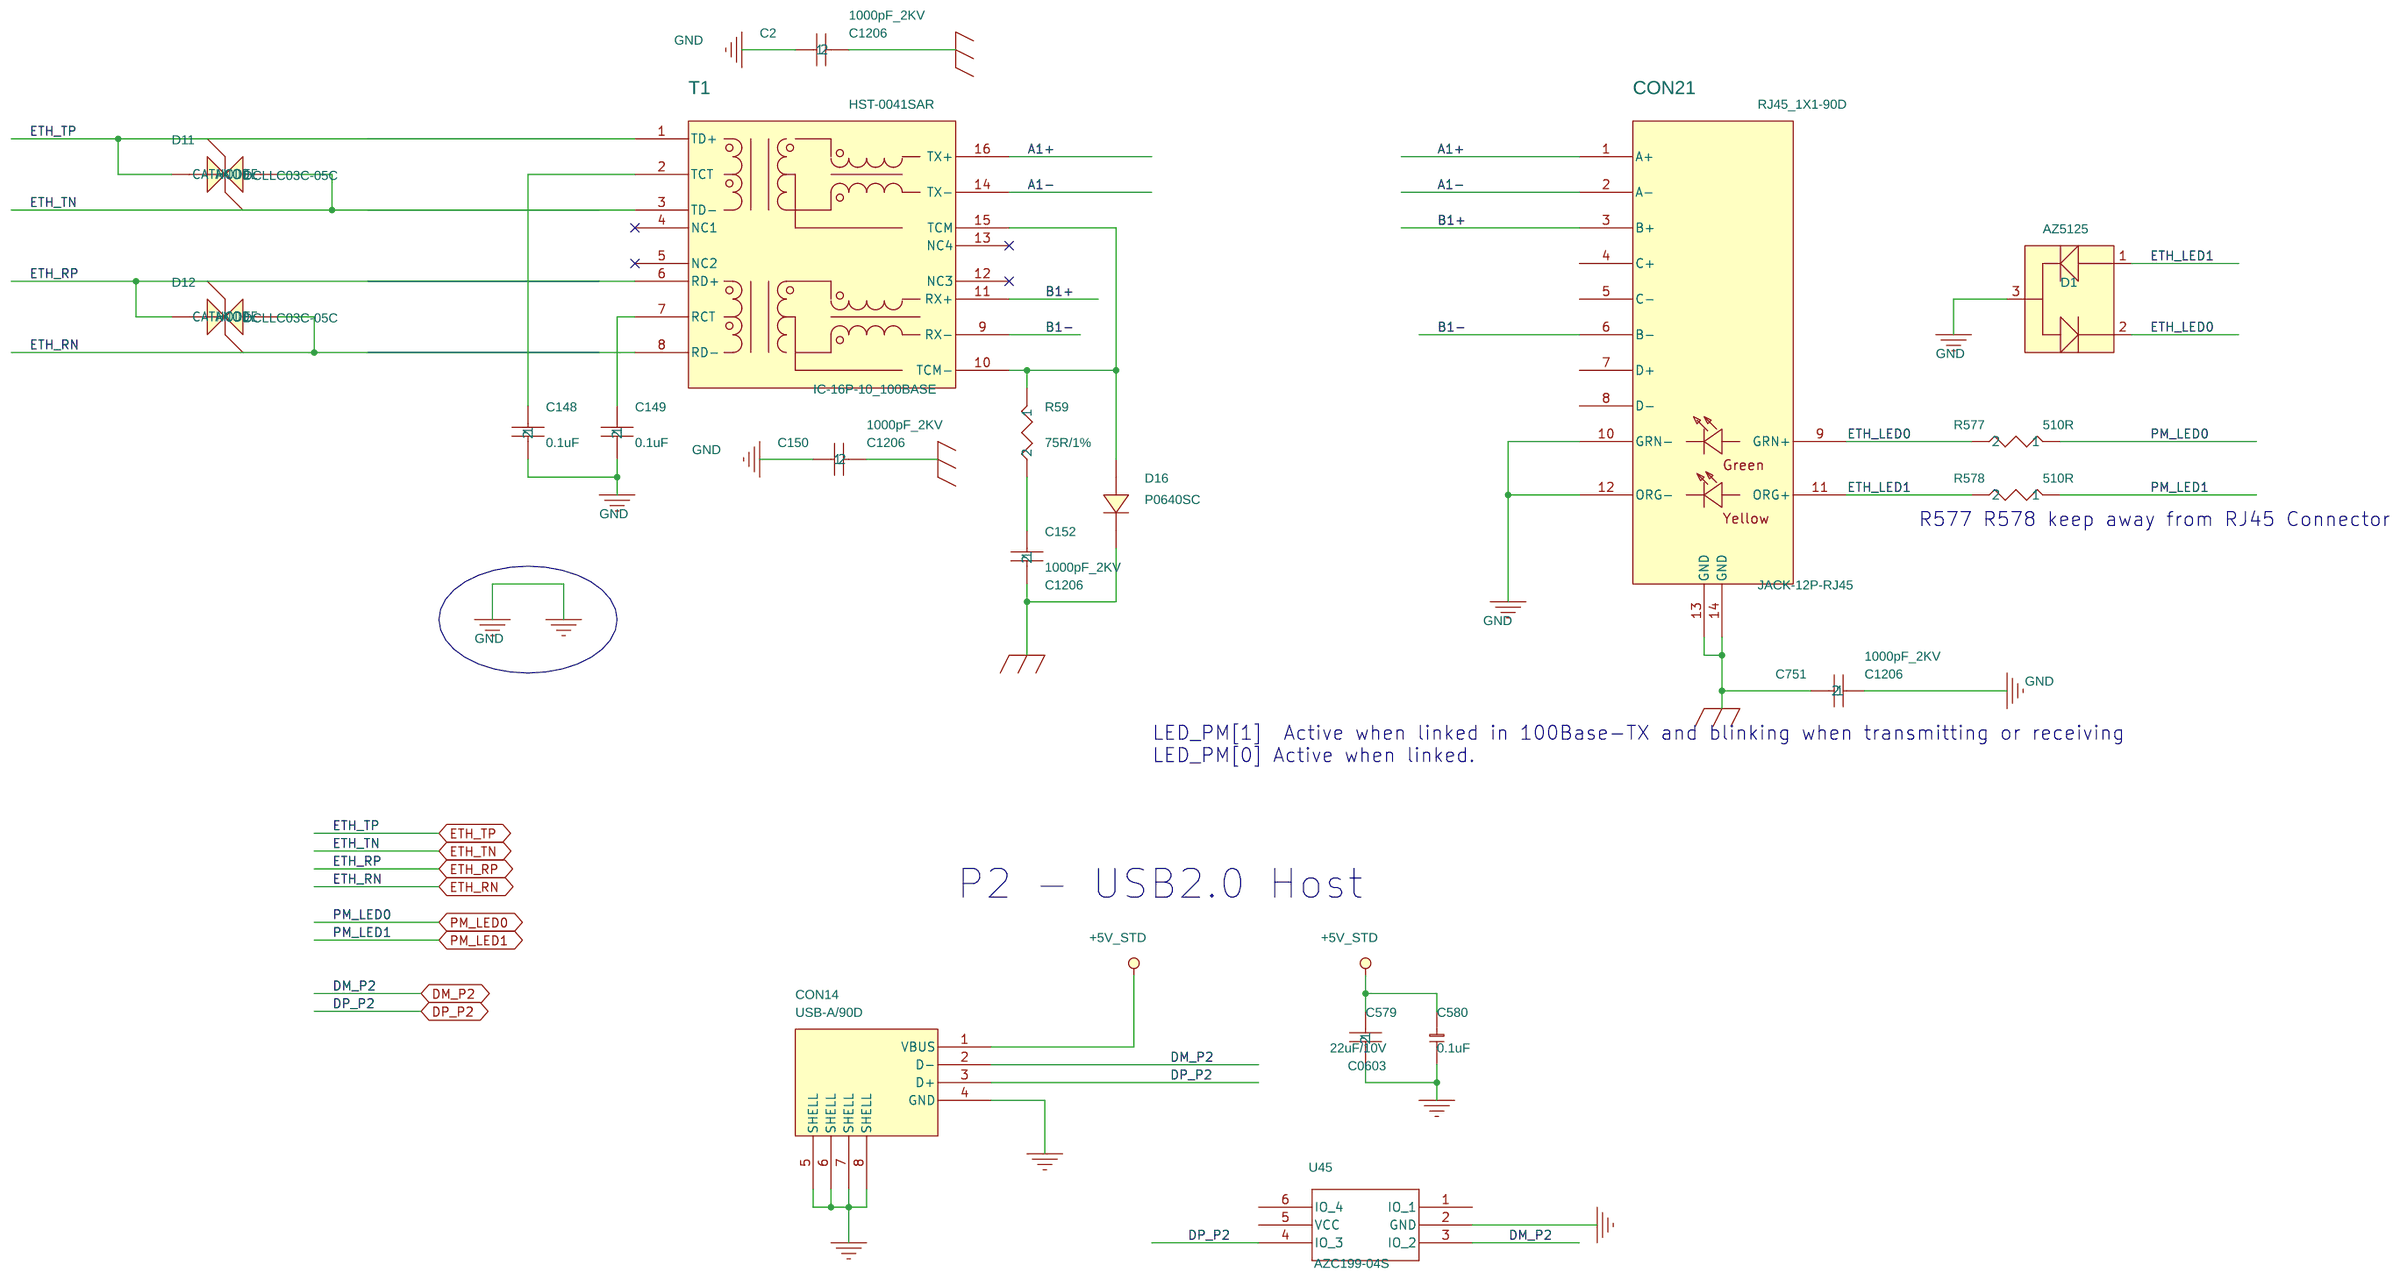
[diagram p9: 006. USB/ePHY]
11 005.UART/RS485/I2C/SPI: size A; note: UART/I2C/SPI
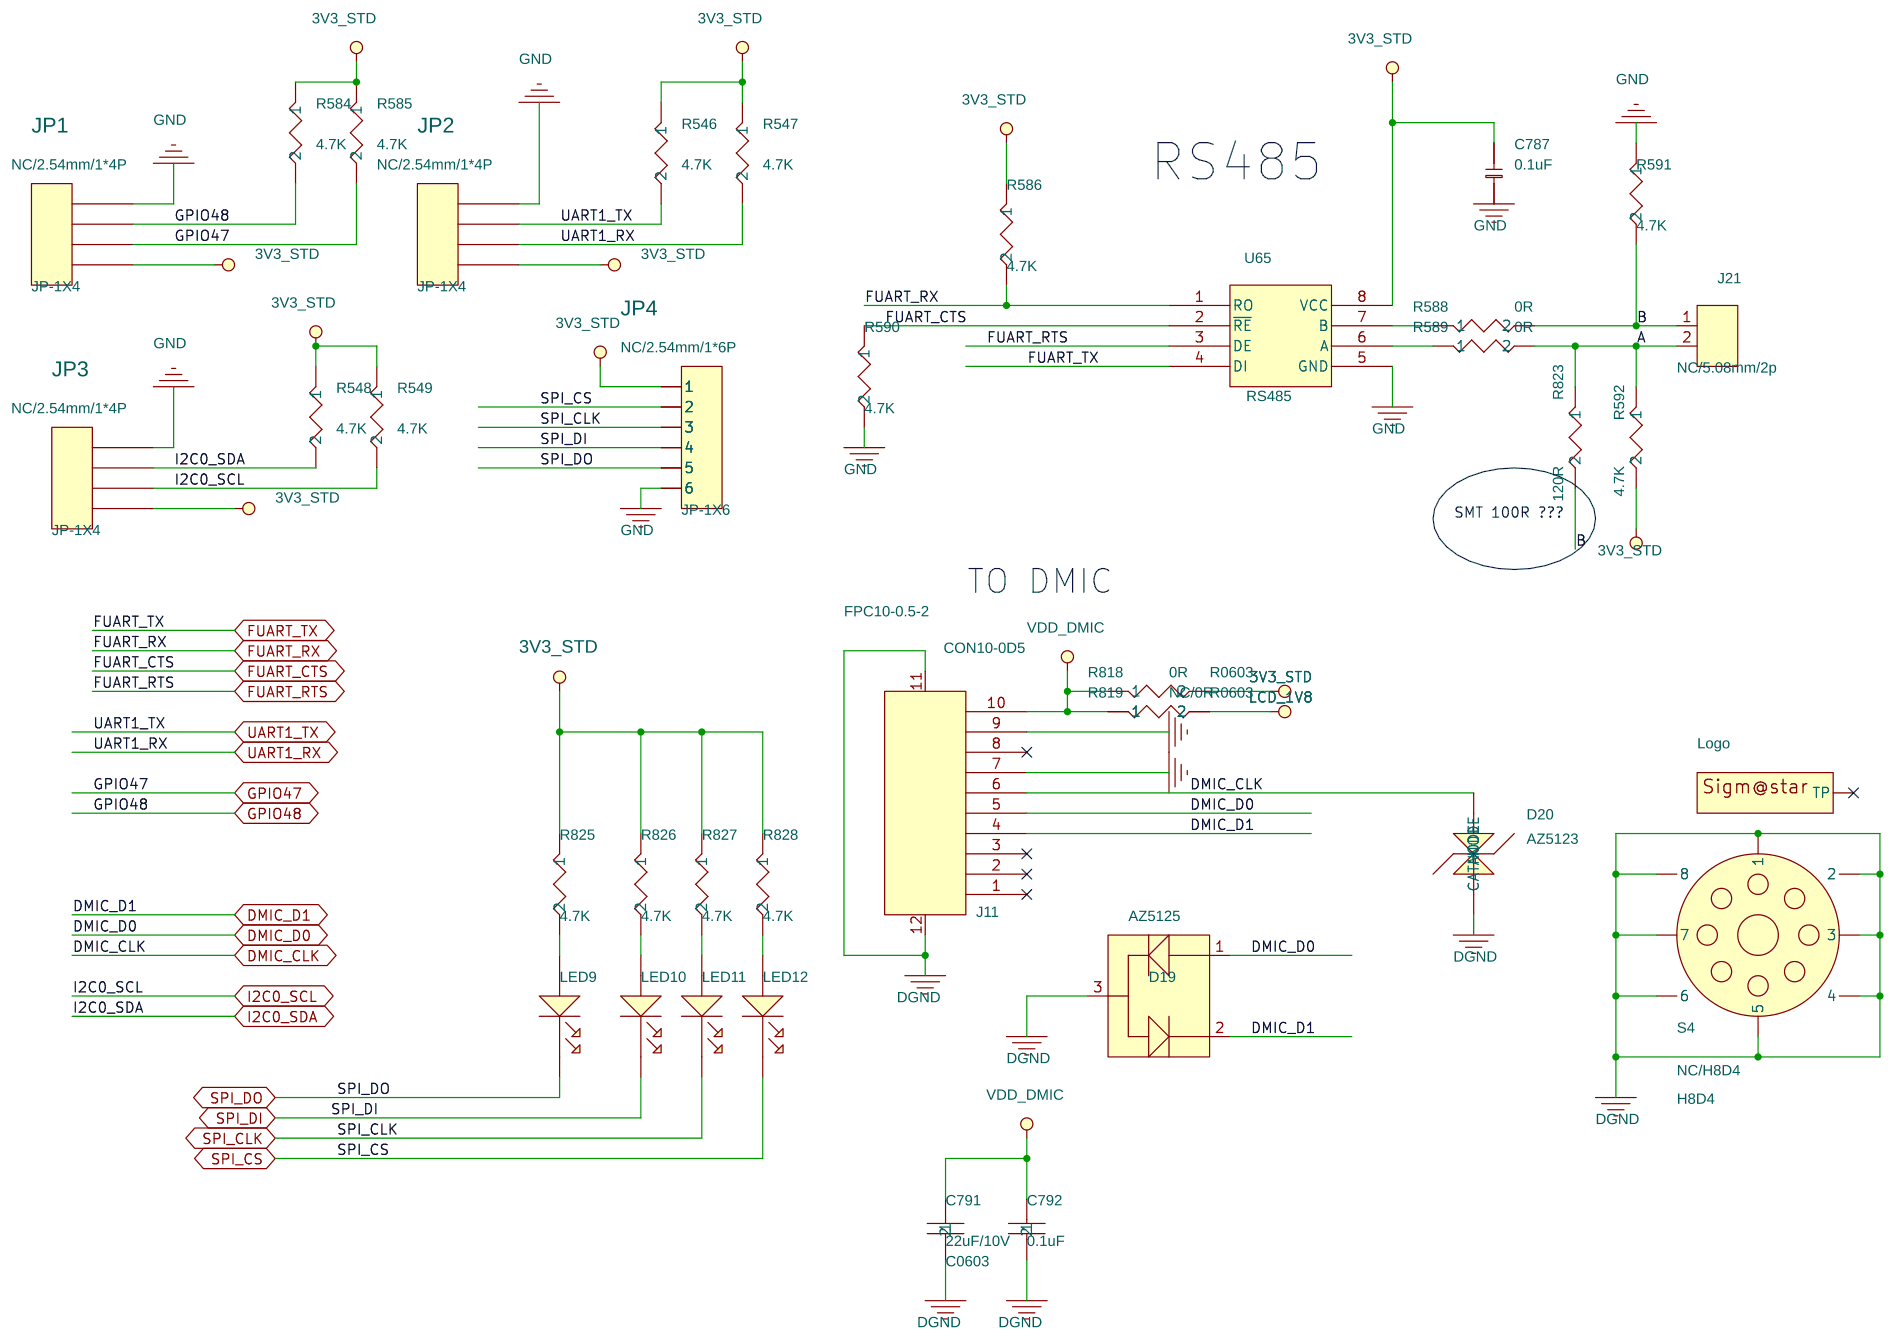
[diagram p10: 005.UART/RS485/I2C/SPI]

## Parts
sheet 003. Power
C1  0.1uF  [C0402]
C3  0.1uF  [C0402]
C4  22uF/10V  [C0603]
C5  0.1uF  [C0402]
C9  22uF/10V  [C0603]
C11  0.1uF  [C0402]
C12  22uF/10V  [C0603]
C13  0.1uF  [C0402]
C14  22uF/10V  [C0603]
C15  0.1uF  [C0402]
C18  22uF/10V  [C0603]
C33  NC/0.1uF  [C0402]
C46  22uF/10V  [C0603]
C47  0.1uF  [C0402]
C48  0.1uF  [C0402]
C49  22uF/10V  [C0603]
C50  0.1uF  [C0402]
C53  0.1uF  [C0402]
C58  0.1uF  [C0402]
C59  0.1uF  [C0402]
C61  NC/22uF/10V  [C0603]
C63  0.1uF  [C0402]
C65  0.1uF  [C0402]
C66  0.1uF  [C0402]
C67  0.1uF  [C0402]
C70  NC/1uF  [C0402]
C71  0.1uF  [C0402]
C84  22uF/10V  [C0603]
C85  22uF/10V  [C0603]
C86  0.1uF  [C0402]
C87  22uF/10V  [C0603]
C89  NC/0.1uF  [C0402]
C90  0.1uF  [C0402]
C91  0.1uF  [C0402]
C92  0.1uF  [C0402]
C93  0.1uF  [C0402]
C94  22uF/10V  [C0603]
C95  22uF/10V  [C0603]
C100  22uF/10V  [C0603]
C104  0.1uF  [C0402]
C105  0.1uF  [C0402]
C255  NC/1uF  [C0402]
C256  1uF  [C0402]
C258  22uF/10V  [C0603]
C260  0.1uF  [C0402]
C638  22uF/10V  [C0603]
C640  0.1uF  [C0402]
C665  0.1uF  [C0402]
C732  0.1uF  [C0402]
C733  NC/47pF  [C0402]
C736  0.1uF  [C0402]
C737  0.1uF  [C0402]
C738  22uF/10V  [C0603]
C739  0.1uF  [C0402]
C741  NC/22uF/10V  [C0603]
C743  NC/39pF  [C0402]
C793  10uF/25V  [C0603]
C795  22uF/10V  [C0603]
C796  22uF/10V  [C0603]
CON1  DC-JACK  [JACK\DC]
D10  BAT54C/WSB5521F-3/TR  [SOT-23]
EC2  470uF/25V  [CE-3.5X8]
JP9  2.54mm/1*2P  [JP-1X2]
K2  Power_KEY  [KEY5X5]
L2  ATNR3015M2R2MTH/1.8A  [L-MLPS-3015]
L5  AMPI0630ED1R0MT/12A  [L-LQH88P]
L8  ATNR4018M2R2MT/2.3A  [L-MLPS-4018]
L94  ATNR3015M2R2MTH/1.8A  [L-MLPS-3015]
LED1  LED_RED-0603  [LED-0603]
Q15  2N7002/WNM7002-3/TR  [SOT-23]
Q16  2N7002/WNM7002-3/TR  [SOT-23]
R1  4.7K  [R0402]
R2  150K/1%  [R0402]
R3  100K/1%  [R0402]
R4  150K/1%  [R0402]
R5  33K/1%  [R0402]
R19  50K/1%  [R0402]
R54  47K  [R0402]
R62  4.7K  [R0402]
R63  47K  [R0402]
R72  100R  [R0402]
R76  4.7K  [R0402]
R107  300K/1%  [R0402]
R183  21K/1%  [R0402]
R231  47K  [R0402]
R232  118K/1%  [R0402]
R234  4.7K  [R0402]
R235  300K/1%  [R0402]
R236  100K/1%  [R0402]
R238  0R  [R0402]
R565  0R  [R0603]
R576  4.7K  [R0402]
R580  NC/4.7K  [R0402]
R593  47K  [R0402]
R831  0R  [R0603]
SW1  Rocker-Switch  [SW-2P-MRA1KKAT0B]
U1  FP6185-1V8/TMI6030-1V8  [SOT-23-5]
U2  TMI3408/FP6396S5  [SOT23-5P]
U3  TMI3408/FP6396S5  [SOT23-5P]
U8  FP6373AS6C  [SOT-23-6L]
U55  FR9855SP  [IC-8P-HTSOP]
sheet 004. SSD201
C7  1uF  [C0402]
C8  0.1uF  [C0402]
C108  10uF  [C0402]
C110  NC/0.1uF  [C0402]
C111  0.1uF  [C0402]
C116  10uF  [C0402]
C118  33pF  [C0402]
C119  33pF  [C0402]
C120  22pF  [C0402]
C121  22pF  [C0402]
C126  0.1uF  [C0402]
C127  22pF  [C0402]
C132  0.1uF  [C0402]
C140  0.1uF  [C0402]
C227  470nF  [C0402]
CON3  2.0mm/1*4p  [B2.0V-L4P]
CON25  CON2-DIP-2.0mm  [DIP1X02PM-80-V]
IR1  NC/IR/RX  [IR]
R22  10K  [R0402]
R23  4.7K  [R0402]
R24  NC/4.7K  [R0402]
R25  4.7K  [R0402]
R26  NC/4.7K  [R0402]
R27  4.7K  [R0402]
R28  NC/4.7K  [R0402]
R29  100R  [R0402]
R30  100R  [R0402]
R42  10K/1%  [R0402]
R43  100R  [R0402]
R44  10K  [R0402]
R45  100R  [R0402]
R53  NC/0R  [R0402]
R71  NC/4.7K  [R0402]
R106  4.7K  [R0402]
R150  100R  [R0402]
R151  100R  [R0402]
R152  100R  [R0402]
R153  100R  [R0402]
R169  100R  [R0402]
R170  100R  [R0402]
R171  100R  [R0402]
R172  100R  [R0402]
R173  100R  [R0402]
R174  100R  [R0402]
R175  100R  [R0402]
R176  100R  [R0402]
R177  100R  [R0402]
R178  100R  [R0402]
R179  100R  [R0402]
R180  100R  [R0402]
R181  100R  [R0402]
R182  100R  [R0402]
R186  100R  [R0402]
R196  100R  [R0402]
R197  100R  [R0402]
R198  100R  [R0402]
R199  100R  [R0402]
R200  100R  [R0402]
R201  100R  [R0402]
R202  100R  [R0402]
R203  100R  [R0402]
R204  100R  [R0402]
R708  0R  [R0402]
R710  0R  [R0402]
R711  0R  [R0402]
R712  0R  [R0402]
R713  0R  [R0402]
R714  0R  [R0402]
R715  0R  [R0402]
R716  0R  [R0402]
R717  0R  [R0402]
R718  0R  [R0402]
R820  0R  [R0402]
R821  4.7K  [R0402]
R822  4.7K  [R0402]
TP60  RES  [TP-0_8MM]
TP61  RES  [TP-0_8MM]
U14  MX35LF1GE4AB  [SOP8-150+208]
U41  SSD201  [MQFN128\0.35-12.3X12.3\z]
Y1  Crystal/[24MHz,18pF]  [XTALS-2_5X3_2MM]
Y2  DST310S/32.768KHz  [XTALS-SMD-3215]
sheet 005.UART/RS485/I2C/SPI
C787  0.1uF  [C0402]
C791  22uF/10V  [C0603]
C792  0.1uF  [C0402]
D19  AZ5125  [SOT23-3L]
D20  AZ5123  [SOD-523]
J11  CON10-0D5  [FPC10-0.5-2]
J21  NC/5.08mm/2p  [5.08-2P]
JP1  NC/2.54mm/1*4P  [JP-1X4]
JP2  NC/2.54mm/1*4P  [JP-1X4]
JP3  NC/2.54mm/1*4P  [JP-1X4]
JP4  NC/2.54mm/1*6P  [JP-1X6]
LED9  LED_RED-0603  [LED-0603]
LED10  LED_RED-0603  [LED-0603]
LED11  LED_RED-0603  [LED-0603]
LED12  LED_RED-0603  [LED-0603]
Logo  NC  [SIGMASTAR-LOGO]
R546  4.7K  [R0402]
R547  4.7K  [R0402]
R548  4.7K  [R0402]
R549  4.7K  [R0402]
R584  4.7K  [R0402]
R585  4.7K  [R0402]
R586  4.7K  [R0402]
R588  0R  [R0402]
R589  0R  [R0402]
R590  4.7K  [R0402]
R591  4.7K  [R0402]
R592  4.7K  [R0402]
R818  0R  [R0603]
R819  NC/0R  [R0603]
R823  120R  [R0402]
R825  4.7K  [R0402]
R826  4.7K  [R0402]
R827  4.7K  [R0402]
R828  4.7K  [R0402]
S4  NC/H8D4  [H8D4]
U65  RS485  [SOIC8]
sheet 006. USB/ePHY
C2  1000pF_2KV  [C1206]
C148  0.1uF  [C0402]
C149  0.1uF  [C0402]
C150  1000pF_2KV  [C1206]
C152  1000pF_2KV  [C1206]
C579  22uF/10V  [C0603]
C580  0.1uF  [C0402]
C751  1000pF_2KV  [C1206]
CON14  USB-A/90D  [USB-4P-A-90D-VT001]
CON21  RJ45_1X1-90D  [JACK-12P-RJ45]
D1  AZ5125  [SOT23-3L]
D11  DCLLC03C-05C  [SOD_323]
D12  DCLLC03C-05C  [SOD_323]
D16  P0640SC  [SMB]
R59  75R/1%  [R0805]
R577  510R  [R0402]
R578  510R  [R0402]
T1  HST-0041SAR  [IC-16P-10_100BASE]
U45  AZC199-04S  [SOT23-6]
sheet 007.SD/SDIO
C587  0.1uF  [C0402]
C590  0.1uF  [C0402]
Q3  AO3401A/WPM3020-3/TR  [SOT-23]
R12  47K  [R0402]
R13  2K  [R0402]
R14  4.7K  [R0402]
R141  0R  [R0402]
R142  47R  [R0402]
R143  47R  [R0402]
R144  47R  [R0402]
R145  47R  [R0402]
R146  47R  [R0402]
R147  47R  [R0402]
SD1  SK10056619  [SK10056619_WGQ]
U67  AZC199-04S  [SOT23-6]
U68  AZC199-04S  [SOT23-6]
sheet 008. Audio
C200  22uF/10V  [C0603]
C201  0.1uF  [C0402]
C202  NC/15nF  [C0402]
C203  1uF  [C0402]
C204  NC  [C0402]
C205  1uF  [C0402]
C206  NC  [C0402]
C747  1uF  [C0402]
C749  390nF  [C0402]
C794  0.1uF  [C0402]
CON22  CON2-DIP-2.0mm  [DIP1X02PM-80-V]
CON23  CON2-DIP-2.0mm  [DIP1X02PM-80-V]
D17  AZ5123  [SOD-523]
D18  AZ5125  [SOT23-3L]
R99  0R  [R0603]
R101  20K  [R0402]
R103  10K  [R0402]
R120  4.7K  [R0402]
R121  NC/1K  [R0402]
R122  2K  [R0402]
R124  NC  [R0402]
R205  NC/0R  [R0402]
R554  0R  [R0402]
R824  10K  [R0402]
S1  NC/H8D4  [H8D4]
S2  NC/H8D4  [H8D4]
S3  NC/H8D4  [H8D4]
TT1  NC/TT  [PV3]
TT2  NC/TT  [PV3]
TT3  NC/TT  [PV3]
U64  SGM4890  [MSOP8]
sheet 009.TTL Panel
C16  0.1uF  [C0402]
C35  0.1uF/50V  [C0402]
C37  22uF/10V  [C0603]
C55  10uF/50V  [C0805]
C263  220nF  [C0402]
C621  0.1uF  [C0402]
C624  NC  [C0603]
C625  0.1uF  [C0402]
C627  1uF/25V  [C0402]
C628  NC/0.1uF  [C0402]
C635  0.1uF  [C0402]
C659  1uF  [C0402]
C675  22uF/10V  [C0603]
C676  0R  [R0402]
C709  NC/0.1uF  [C0402]
C782  10uF/25V  [C0603]
C783  10uF/25V  [C0603]
C784  10uF/25V  [C0603]
C785  10uF/25V  [C0603]
CON2  FPC_6PINB_Up_Type  [FPC_6PINB]
D2  BAT54S/WSB5522F-3/TR  [SOT-23]
D3  WSB5543W-2/TR  [SOD-323HE]
D4  WSB5543W-2/TR  [SOD-323HE]
D5  BAT54S/WSB5522F-3/TR  [SOT-23]
D6  NC/BAT54S/WSB5522F-3/TR  [SOT-23]
D21  MM1Z6V2/0.5W  [SOD123]
D22  MM1Z18/0.5W  [SOD123]
J15  FPC-CON50_Down_Type  [IL-FHR-50S]
L4  ATNR4018M4R7MT/2.3A  [L-MLPS-4018]
L35  ATNR4018M4R7MT/2.3A  [L-MLPS-4018]
Q12  AO3401A/WPM3020-3/TR  [SOT-23]
R6  4.7K  [R0402]
R9  5R/1%  [R0805]
R11  100K/1%  [R0402]
R52  47K  [R0402]
R81  47K  [R0402]
R108  100R  [R0402]
R109  24K/1%  [R0402]
R110  3.3K/1%  [R0402]
R111  10K  [R0402]
R212  4.7K  [R0402]
R214  10K  [R0402]
R215  100R  [R0402]
R216  20K  [R0402]
R217  4.7K  [R0402]
R218  NC/4.7K  [R0402]
R219  10K  [R0402]
R561  0R  [R0603]
R562  0R  [R0603]
R568  NC/4.7K  [R0402]
R569  4.7K  [R0402]
R570  NC/4.7K  [R0402]
R571  4.7K  [R0402]
R572  4.7K  [R0402]
R573  NC/4.7K  [R0402]
R574  4.7K  [R0402]
R575  NC/4.7K  [R0402]
R583  0R  [R0603]
R835  5R/1%  [R0805]
R836  0R  [R0603]
TP17  RES  [TP-0_8MM]
TP18  RES  [TP-0_8MM]
U4  FP6736S5GTR  [SOT23-5P]
U6  FP6755S6CTR  [IC-6P-TSOT23]
U69  AZC199-04S  [SOT23-6]
VCOM  TP  [TP-0_6MM]
VR2  50K  [VR-3296W]
sheet 010.USB_WIFI
C114  1uF  [C0402]
C117  1uF  [C0402]
C180  1uF  [C0402]
C181  0.1uF  [C0402]
C716  22pF  [C0402]
C717  NC/10pF  [C0402]
C719  1uF  [C0402]
C720  1uF  [C0402]
C721  1uF  [C0402]
C722  1uF  [C0402]
C723  1uF  [C0402]
C724  1uF  [C0402]
C725  22uF/10V  [C0603]
C726  0.1uF  [C0402]
C728  1pF  [C0402]
C729  0.5pF  [C0402]
C745  8.2pF  [C0402]
C746  8.2pF  [C0402]
C802  0.1uF  [C0402]
C803  0.1uF  [C0402]
C805  200pF  [C0402]
J4  IPEX1  [KK23011-02-7H]
L96  2nH  [L0402]
L97  1.2nH  [L0402]
Q17  NC/AO3401A/WPM3020-3/TR  [SOT-23]
R15  0R  [R0402]
R16  0R  [R0402]
R17  10K  [R0402]
R21  12K/1%  [R0402]
R223  4.7K  [R0402]
R240  0R  [R0402]
R556  4.7K  [R0402]
R557  4.7K  [R0402]
R559  0R  [R0402]
R566  0R  [R0603]
R832  47K  [R0402]
R833  0R  [R0402]
R834  200R  [R0402]
TP12  Debug_RX  [TP]
TP14  GPIO20  [TP]
TP15  GPIO21  [TP]
TP52  Debug_TX  [TP]
U10  NC/BL-M8188FU3-B  [BL-M8188FU3-B]
U11  SSW101B  [IC-28P-QFN-4x4-P04]
VR1  NC/DCE0510D2LC  [R0402]
Y3  Crystal/[24MHz,18pF]  [XTALS-2_5X3_2MM]
sheet 011.RMII
C157  1000pF_2KV  [C1206]
C158  1000pF_2KV  [C1206]
C159  1000pF_2KV  [C1206]
C160  0.1uF  [C0402]
C161  0.1uF  [C0402]
C251  33pF  [C0402]
C252  33pF  [C0402]
C253  10uF  [C0402]
C254  0.1uF  [C0402]
C797  0.1uF  [C0402]
C798  10uF  [C0402]
C799  10uF  [C0402]
C800  0.1uF  [C0402]
C801  0.1uF  [C0402]
CON7  RJ45_1X1-90D  [JACK-12P-RJ45]
D13  DCLLC03C-05C  [SOD_323]
D14  DCLLC03C-05C  [SOD_323]
D15  P0640SC  [SMB]
R10  4.7K  [R0402]
R34  100R  [R0402]
R35  4.7K  [R0402]
R37  0R  [R0402]
R38  4.7K  [R0402]
R39  6.19K/1%  [R0402]
R40  100R  [R0402]
R41  4.7K  [R0402]
R47  4.7K  [R0402]
R51  4.7K  [R0402]
R55  470K  [R0402]
R56  75R/1%  [R0805]
R57  0R  [R0603]
R829  4.7K  [R0402]
R830  0R  [R0402]
T4  HST-0041SAR  [IC-16P-10_100BASE]
U66  IP101GR  [QFN32_IP101G_DS_R04]
Y4  25M20PI/49US  [XTALS]

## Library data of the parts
C1 = CAP_NP2_23
C3 C16 = CAP_NP_6: BOM: SMD CAP 0402 X7R 1nF 10V +/-20%
C4 C579 C784 C791 = CAP_NP: BOM: SMD CAP 0805 Y5V 10uF 6V +80~-20%
C5 = CAP_NP_7: BOM: SMD CAP 0402 X7R 1nF 10V +/-20%
C9 C11-C15 C258 C260 C787 = C0402_100nF_10V_X7R
C18 = CAP_NP2_25
C33 = CAP_NP2_19
C46 = CAP_NP2_21
C47 = CAP_NP2_17
C48 C140 C160 C202 C621 C751 = CAP_NP2
C49 = CAP_NP2_27
C50 C111 = CAP_NP2_9
C53 = CAP_NP2_20
C58 C126 C205 = CAP_NP2_7
C59 C121 C149 C158 C204 = CAP_NP2_2
C2 C61 C118 C794 = CAP_NP2_5
C63 C580 C665 C736-C739 = C0402: Vendor: MURATA
C65 = CAP_NP2_18
C66 = CAP_NP2_14
C67 = CAP_NP2_28
C70 = CAP_NP2_16
C71 = CAP_NP2_15
C84 = CAP_NP2_31
C85 = CAP_NP2_10
C86 = CAP_NP2_29
C87 C120 C206 = CAP_NP2_6
C89 = CAP_NP2_30
C90 = CAP_NP2_22
C91 C110 C148 C161 C201 = CAP_NP2_1
C92 = CAP_NP2_26
C93 C152 C159 C200 C227 = CAP_NP2_4
C94 = CAP_NP2_13
C95 C119 C150 C157 C203 = CAP_NP2_3
C100 = CAP_NP2_12
C104 C127 = CAP_NP2_8
C105 = CAP_NP_2
C255 = CAP_NP2_11
C256 = CAP_NP2_24
C638 = CAP_NP_9: Vendor: MURATA
C640 C797 = CAP_NP_4: Vendor: MURATA
C732 C733 = CAP: Vendor: MURATA
C252 C741 = CAP_NP_5: Vendor: MURATA
C743 = C0402_100pF_50V_X7R: Vendor: MURATA
C8 C793 C799 = CAP_NP_3: Vendor: MURATA
C116 C254 C795 = CAP_NP_1: Vendor: MURATA
C251 C796 = CAP_NP_8: Vendor: MURATA
CON1 = DC-JACK
D10 = BAT54C_SOT_0
EC2 = C-DIP_470uF_25V
JP9 = HEADER_4_0
K2 = PUSHBUTTON_STS_0
L2 L94 = CHOKE_4.7uH_4.1A-L8.0W8.0H4.0: [ 4.7uH/4100mA ]; Inductance:4.7uH+-30%;Rated Current:4100mA;Self-resonant Frequency:30MHz;DC.Resistance:0.018R+-30%;
L4 L5 L8 L35 = INDUCTOR_IRON_0: BOM: MNR-6045-4R7N
LED1 LED9-LED12 = LED_Green-0603
Q15 Q16 = AO3400_SOT23
R1 R34 R124 R172 R548 R571 R577 = R_1
R2-R5 R14 R52 R81 R101 R103 R108-R111 R215 R216 R824 = R-PIN-Mark
R19 R234-R236 R576 = R0402: Vendor: YAGEO
R54 = R2
R62 = R2_1
R63 = R5
R72 = R5_1
R55 R76 R121 R186 R549 R835 = R_3
R39 R107 R176 R554 R588 = R_6
R183 = R_8: Assembly: R0603; Vendor: YAGEO
R231 = R_7: Assembly: R0603; Vendor: YAGEO
R232 = R_2: Assembly: R0603; Vendor: YAGEO
R35 R59 R204 R205 R238 R566 R568 R586 = R
R40 R196 R565 R574 R819 = R_9
R57 R99 R175 R580 R583 R590 = R_4
R593 = R2_2
R120 R572 R712 R828 R830 R831 = R_5
SW1 = Rocker_Switches
U1 = MIC5207_0: BOM Value: EUP7967AVIR1 (ADJ)1.3V/300mA SOT-25 EUTECH; PRICE: 0.1456
U2 U3 = LDO,iD9306-AD,300mA_3: iD9306-AD; Part Number: 300035100G; Specification: SOT23,1.8V,ROHS
U8 = DC_DC_SY8113_18V-3A_TSOT23-6_5: [3A/1.8V,400kHz](Step Down); High Efficiency 400kHz, 2A Synchronous Step Down Regulator.
U55 = FR9855_1
C7 C800 = CAP_NP_2: Vendor: MURATA
C108 C253 = CAP_NP: Vendor: MURATA
C132 = C0402
CON3 = HEADER_1x4-2mm_180D
CON23 CON25 = HEADER_1x4-2mm_0
IR1 = IR_RX_MSTAR
R22 = R_26
R23 R218 R547 = R_16
R24 = R_45
R25 R562 R827 = R_18
R26 = R_47
R27 = R_19
R28 = R_48
R29 = R_49
R30 = R_39
R42 = R_43
R43 R56 R569 R591 = R_8
R44 = R_42
R45 = R_32
R38 R53 R122 R141-R147 R578 R825 R836 = R_2
R71 R106 = R0402: BOM: RES: 33£[, 5%, 0603
R9 R150 R818 = R_15
R151 = R_40
R152 R561 R589 = R_11
R153 = R_36
R169 R570 R823 = R_17
R170 = R_41
R171 R575 R826 = R_13
R51 R173 R219 R584 = R_7
R174 R217 R592 = R_12
R177 = R_22
R178 = R_35
R179 = R_24
R180 = R_54
R181 = R_28
R182 = R_46
R197 = R_21
R198 = R_31
R199 = R_23
R200 = R_50
R201 = R_27
R202 = R_51
R203 = R_37
R708 = R_29
R710 = R_33
R711 = R_44
R713 = R_34
R6 R546 R714 = R_14
R715 = R_53
R716 = R_25
R573 R585 R717 = R_10
R718 = R_20
R820 = R_30
R821 = R_38
R822 = R_52
TP17 TP18 TP60 TP61 = TEST_POINT_0
U14 = 24C08_0
U41 = P2_QFN128_9
Y1 Y3 = OSC-20MHz_HALF_0
Y2 = CRYSTAL-2pin_0
C792 = CAP_NP_1: BOM: SMD CAP 0402 X7R 1nF 10V +/-20%
D1 D2 D5 D6 D18 D19 = DAN217U_1
D11-D14 D17 D20 = DIODE_0: Details: 贴片ESD静电保护器件-SLC05C-SOD-323; Itemid: 004030300006
J11 = AIC1734-xxPU_3
J21 = 5.08mm_1*2p
JP1-JP3 = 3CON100_3
JP4 = HEADER_2_0
Logo = T_POINT_2
S3 S4 = HOLE-V8_1
U65 = RS485
CON14 = USB_1x1-B_TYPE-90D_0: BOM: DIP-CON USB 1PORT (B-TYPE)
CON7 CON21 = RJ45_0: BOM: 8108CS-B111; Part-type: RJ45
D15 D16 = DIODE
T1 T4 = 10_100BASE-TX_LAN_MAGNETIC
U45 U67-U69 = AZC199-04S
C587 C590 C725 C726 C802 C803 = C0402: BOM: CAP: 22nF, 0603
Q3 Q12 Q17 = SMD_NMOS_SOT-23DGS_1
R12 R17 R832 = R0402_100K_1%
R13 R15 R16 R240 R559 R834 = R0402
SD1 = SKTSD-KALER-TF01A-K3: TF-CON;CARD;T-FLASH,13Pin,TOP,Receptacle/Reader,Single,1.1mm,H2.0mm,R/A,GOLD 3u",LCP; P/N: 291220000015
C263 C624 C625 C627 C628 C659 C676 C747 C749 = C0805_10uF
CON22 = HEADER_1x4-2mm_0_1
S1 = HOLE-V8_1_2
S2 = HOLE-V8_1_1
TT1-TT3 = TT
U64 = TS4890IST_0
C35 = CAP_NP_9: BOM: SMD CAP 0402 X7R 1nF 10V +/-20%
C37 = CAP_NP_5: BOM: SMD CAP 0805 Y5V 10uF 6V +80~-20%
C55 = CAP_NP_7: BOM: SMD CAP 0805 Y5V 10uF 6V +80~-20%
C635 = C
C675 = CAP_NP_8: BOM: SMD CAP 0805 Y5V 10uF 6V +80~-20%
C709 = CAP_NP_4: BOM: SMD CAP 0402 X7R 1nF 10V +/-20%
C782 = CAP_NP_2: BOM: SMD CAP 0805 Y5V 10uF 6V +80~-20%
C783 = CAP_NP_1: BOM: SMD CAP 0805 Y5V 10uF 6V +80~-20%
C785 = CAP_NP_3: BOM: SMD CAP 0805 Y5V 10uF 6V +80~-20%
CON2 = HEADER_20X2_3
D3 D4 = 1N5819HW: Comment: 600W SMB TVS
D21 D22 = DIODE_ZENER13_0: ROOM: LCD-AVDD
J15 = CON50pin_5
R11 = R_6: BOM: SMD RES 0402 10K 5% 1/16W
R41 R212 = RESISTOR_1
R37 R214 = RESISTOR
U4 = ssc2213_0
U6 = MIC4576_2
VCOM = TEST_POINT_1
VR2 = RESISTOR_VAR
C114 C181 C716 C717 C723 C724 C745 C746 C805 = C_0603
C117 C180 C719-C722 C728 C729 = C_0402
J4 = SMA-3pin_0
L96 L97 = L_0402
R21 R223 R556 R557 R833 = R_0402(H)
TP12 TP14 TP15 TP52 = T_POINT_R
U10 = WIFI: PKG_TYPE: WL-UM01C-7601
U11 = SV6X55P_48P_6X6_0
VR1 = DIODE_BI-DIR_TRIG
C798 = CAP_NP_7: Vendor: MURATA
C801 = CAP_NP_6: Vendor: MURATA
R10 = RESISTOR_3
R47 = RESISTOR_4
R829 = RESISTOR_2
U66 = IP101GR_0
Y4 = CRYSTAL

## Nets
1V0_Normal: C18.1 C63.1 C84.1 C85.1 C86.1 C87.1 C89.1 C90.1 C91.1 C92.1 C93.1 C94.1 C95.1 C100.1 C105.1 C111.1 C741.1 C743.1 C796.1 L8.2 R19.2 R53.1 U41.4(VDD_1V0) U41.12(VDD_1V0) U41.25(VDD_1V0) U41.42(VDD_1V0) U41.49(DVDD_DDR_1V0) U41.51(VDD_1V0) U41.77(VDD_1V0) U41.78(VDD_1V0) U41.105(VDD_1V0)
1V5_STD: C9.2 C11.2 C33.1 C61.1 C67.1 C70.1 C71.1 L2.2 R2.1 U41.40(VDDIO_CMD_1V5) U41.41(AVDDIO_DRAM_1V5) U41.43(VDDIO_MCLK_1V5) U41.44(VDDIO_DATA_1V5) U41.45(VDDIO_DATA_1V5) U41.46(AVDDIO_DRAM_1V5)
1V8_STD: C4.1 C5.1 R565.1 U1.5(OUT)
3V3_STD: C1.1 C3.1 C7.1 C8.1 C46.1 C47.1 C48.1 C49.1 C50.1 C53.1 C58.1 C65.1 C66.1 C116.1 C132.1 C255.1 C256.1 C258.2 C260.2 C787.2 C798.1 C799.1 C800.1 C801.1 CON2.6 J15.7(VCC) JP1.1 JP2.1 JP3.1 JP4.1 L94.2 Q3.2(SOURCE) Q17.2(SOURCE) R1.1 R4.1 R6.1 R12.2 R14.2 R23.2 R25.2 R27.2 R35.2 R38.2 R41.2 R47.2 R55.1 R62.1 R71.2 R76.1 R106.1 R120.1 R217.1 R218.1 R219.1 R234.1 R546.1 R547.1 R548.1 R549.1 R566.1 R568.1 R570.1 R572.1 R574.1 R584.1 R585.1 R586.1 R592.2 R818.2 R821.2 R822.2 R825.1 R826.1 R827.1 R828.1 R830.1 R831.1 R832.2 U1.1(IN) U1.3(EN) U14.8(VCC) U41.11(VDDP0_3V3) U41.13(AVDD_XTAL_3V3) U41.17(AVDD_RTC_3V3) U41.23(AVDD_NODIE_3V3) U41.48(AVDD_PLL_3V3) U41.64(AVDD_USB_3V3) U41.76(VDDP1_3V3) U41.98(VDDP1_3V3) U41.106(AVDD_ETH_3V3) U41.113(AVDD3P3_USB_3V3) U65.8(VCC) U66.13(DVDD33_IO) U66.31(AVDD33)
3V3_WIFI: C117.1 C180.1 C719.1 C720.1 C721.1 C722.1 C723.1 C724.1 C725.1 C726.1 C802.1 C803.1 Q17.3(DRAIN) R17.1 R557.1 R566.2 U10.1(VCC) U11.8(DVDDIO) U11.9(UVDD33) U11.20(DVDD) U11.21(AVDD) U11.22(AVDD) U11.24(AVDD) U11.25(AVDD) U11.28(AVDD)
5V_BST: C675.1 L35.1 Q12.1(GATE) R111.1 R583.2 U4.5(VIN)
+5V_STD: C12.2 C13.2 C14.2 C15.2 C579.1 C580.1 C638.1 C640.1 C733.2 C738.1 C739.1 C795.1 CON14.1(VBUS) L5.2 R44.2 R45.2 R99.2 R212.1 R231.1 R232.2 R561.1 R576.2 R583.1 U2.1(EN) U2.4(Vin) U3.1(EN) U3.4(Vin) U8.4(IN)
+12V_Normal: C104.1 C736.1 C793.1 EC2.1 K2.1 K2.2 R593.1 SW1.2(ON) U55.8(VIN)
AVDD1P2_MIPI: C140.1 U41.75(AVDD1P2_MIPI)
AVDD_AUD: C59.1 R831.2 U41.114(AVDD_AUD_3V3)
DVDD_DDR_RX: C110.1 C227.1 R53.2 U41.50(DVDD_DDR_RX)
GND: C1.2 C2.1 C3.2 C4.2 C5.2 C7.2 C8.2 C9.1 C11.1 C12.1 C13.1 C14.1 C15.1 C16.1 C18.2 C33.2 C35.2 C37.2 C46.2 C47.2 C48.2 C49.2 C50.2 C53.2 C55.2 C58.2 C59.2 C61.2 C63.2 C65.2 C66.2 C67.2 C70.2 C71.2 C84.2 C85.2 C86.2 C87.2 C89.2 C90.2 C91.2 C92.2 C93.2 C94.2 C95.2 C100.2 C104.2 C105.2 C110.2 C111.2 C114.1 C117.2 C118.2 C119.2 C120.2 C121.2 C126.2 C127.2 C132.2 C140.2 C148.2 C149.2 C150.1 C158.1 C159.1 C160.2 C161.2 C180.2 C181.2 C200.2 C201.2 C202.2 C204.2 C205.1 C206.2 C227.2 C251.2 C252.2 C253.2 C254.2 C255.2 C256.2 C258.1 C260.1 C579.2 C580.2 C590.2 C625.2 C627.2 C635.2 C638.2 C640.2 C659.2 C665.2 C675.2 C676.2 C709.2 C716.2 C717.2 C719.2 C720.2 C721.2 C722.2 C723.2 C724.2 C725.2 C726.2 C728.2 C729.2 C736.2 C737.2 C738.2 C739.2 C741.2 C745.1 C746.1 C747.2 C751.1 C782.2 C783.2 C784.2 C785.2 C787.1 C791.2 C792.2 C793.2 C794.2 C795.2 C796.2 C797.2 C798.2 C799.2 C800.2 C801.2 C802.2 CON1.2 CON1.3 CON2.5 CON2.7 CON2.8 CON3.2 CON7.12(ORG-) CON14.4(GND) CON14.5(SHELL) CON14.6(SHELL) CON14.7(SHELL) CON14.8(SHELL) CON21.10(GRN-) CON21.12(ORG-) CON23.2 CON25.2 D1.3 D6.2 D17.2(CATHODE) D18.3 D19.3 D20.2(CATHODE) D21.2(CATHODE) D22.1(ANODE) EC2.2 IR1.2 J4.2(GND1) J4.3(GND2) J11.7 J11.9 J11.11 J11.12 J15.5(GND) J15.36(GND) J15.38(GND) J15.48(GND) J15.51(GND) J15.52(GND) JP1.4 JP2.4 JP3.4 JP4.6 LED1.2 Q15.2(SOURCE) Q16.2(SOURCE) R3.1 R5.1 R9.2 R10.2 R13.2 R21.1 R22.2 R24.2 R26.2 R28.2 R39.2 R42.2 R51.2 R52.2 R63.1 R81.2 R107.1 R110.2 R121.2 R124.2 R183.2 R214.2 R216.2 R223.1 R236.1 R556.1 R569.1 R571.1 R573.1 R575.1 R580.2 R590.2 R591.1 R820.2 R829.1 R835.2 S1.1 S1.2 S1.3 S1.4 S1.5 S1.6 S1.7 S1.8 S2.1 S2.2 S2.3 S2.4 S2.5 S2.6 S2.7 S2.8 S3.1 S3.2 S3.3 S3.4 S3.5 S3.6 S3.7 S3.8 S4.1 S4.2 S4.3 S4.4 S4.5 S4.6 S4.7 S4.8 SD1.6(VSS) SD1.10(G) SD1.11(GND1) SD1.12(GND2) SD1.13(GND3) TT1.1 TT2.1 TT3.1 U1.2(GND) U2.2(GND) U3.2(GND) U4.2(GND) U6.2(GND) U8.2(GND) U10.4(GND) U10.5(GND) U11.12(UVSS33) U11.29(E-PAD) U14.4(GND) U41.47(AVSSIO_DQ_GND) U41.129(ePAD) U45.2(GND) U55.5(GND) U55.9(GND1) U64.7(GND) U65.5(GND) U66.33(GND) U67.2(GND) U68.2(GND) U69.2(GND) VR1.1 Y1.2(GND) Y1.4(GND) Y3.2(GND) Y3.4(GND)
GND_EARTH_EPHY: C2.2 C150.2 C152.2 C751.2 CON21.13(GND) CON21.14(GND) D16.2(K)
GND_EARTH_EPHY_1: C157.2 C158.2 C159.2 CON7.13(GND) CON7.14(GND) D15.2(K)
GND_EFUSE: R42.1 U41.24(GND_EFUSE)
VCC12V_EN: D10.3(C) JP9.1 U55.1(~{SHDN})
VDD_DMIC: C791.1 C792.1 J11.10 R818.1 R819.1
50MHz_CLKOUT: R37.2 U66.10(TXCLK/50M_CLKI) U66.14(RX_CLK/50M_O)
A: J21.2 R589.2 R592.1 R823.1
A1+: CON21.1(A+) T1.16(TX+)
A1-: CON21.2(A-) T1.14(TX-)
ANT: R559.2 U11.23(ANT)
AUD_LINEOUT_L: R205.2 U41.116(AUD_LINEOUT_L0)
AUD_LINEOUT_R: C749.1 U41.115(AUD_LINEOUT_R0)
AUD_MICCM0: C205.2 C206.1 U41.117(AUD_MICCM0)
AUD_MICIN0: C203.2 C204.1 U41.118(AUD_MICIN0)
AUD_VAG: C108.2 U41.120(AUD_VAG)
AUD_VRM: C108.1 R820.1 U41.119(AUD_VRM)
Audio_EN: R824.1 U41.1(GPIO12)
B: J21.1 R588.2 R591.2 R823.2
B1+: CON21.3(B+) T1.11(RX+)
B1-: CON21.6(B-) T1.9(RX-)
BL_FB: R9.1 R835.1 R836.1 U6.3(FB)
BL_LED+: J15.1(VLED+) J15.2(VLED+) R562.2 TP17.1
BL_LED-: J15.3(VLED-) J15.4(VLED-) R836.2 TP18.1
BL_OVP: C35.1 C55.1 D4.2(C) R562.1 U6.5(NC)
CRS: R829.2 U66.20(CRS/LEDMOD)
DCIN-JACK: CON1.1 SW1.1(OFF)
DITHB: J15.47(DITHB) R568.2 R569.2
DM_P1: R16.1 U10.2(D-) U41.63(DM_P1)
DM_P2: CON14.2(D-) U41.112(DM_P2) U45.3(IO_2)
DMIC_CLK: D20.1(ANODE) J11.6 U41.9(DMIC_CLK)
DMIC_D0: D19.1 J11.5 U41.8(DMIC_L)
DMIC_D1: D19.2 J11.4 U41.7(DMIC_R)
DP_P1: R15.1 U10.3(D+) U41.62(DP_P1)
DP_P2: CON14.3(D+) U41.111(DP_P2) U45.4(IO_3)
EDGSL_RL: J15.39(L/R) R572.2 R573.2
ET_RX_ER-E: R47.1 U66.21(RXER/INTR_32)
ETH_LED0: CON21.9(GRN+) D1.2 R577.2
ETH_LED1: CON21.11(ORG+) D1.1 R578.2
ETH_RN: D12.1(ANODE) T1.8(RD-) U41.107(ETH_RN)
ETH_RP: D12.2(CATHODE) T1.6(RD+) U41.108(ETH_RP)
ETH_TN: D11.1(ANODE) T1.3(TD-) U41.109(ETH_TN)
ETH_TP: D11.2(CATHODE) T1.1(TD+) U41.110(ETH_TP)
FUART_CTS: R590.1 U41.54(FUART_CTS) U65.2(~{RE})
FUART_RTS: U41.55(FUART_RTS) U65.3(DE)
FUART_RX: R586.2 U41.52(FUART_RX) U65.1(RO)
FUART_TX: U41.53(FUART_TX) U65.4(DI)
GPIO47: JP1.2 R585.2 U41.36(GPIO47)
GPIO48: JP1.3 R584.2 U41.37(GPIO48)
HSDM: C745.2 R16.2 U11.11(DM)
HSDP: C746.2 R15.2 U11.10(DP)
I2C0_SCL: JP3.2 R549.2 U41.123(GPIO6(I2C0_SCL))
I2C0_SDA: JP3.3 R548.2 U41.124(GPIO7(I2C0_SDA))
INV_UD: J15.40(U/D) R570.2 R571.2
IR: C127.1 IR1.1 R43.2 R44.1
IR_PWR: C126.1 IR1.3 R45.1
LCD_1V8: J15.49(NC) J15.50(NC) R565.2 R819.2
LCD_5V: C37.1 L4.1 R11.1 R561.2 U6.6(VIN)
LCD_B0: J15.28(R7) R186.2
LCD_B1: J15.29(R6) R196.2
LCD_B2: J15.30(R5) R199.2
LCD_B3: J15.31(R4) R197.2
LCD_B4: J15.32(R3) R201.2
LCD_B5: J15.33(R2) R198.2
LCD_B6: J15.34(R1) R203.2
LCD_B7: J15.35(R0) R200.2
LCD_BL_PWM: R11.2 U6.4(ON/~{OFF}) U41.121(GPIO4(PWM0))
LCD_DE: J15.9(DE) R153.2
LCD_G0: J15.20(G7) R176.2
LCD_G1: J15.21(G6) R174.2
LCD_G2: J15.22(G5) R179.2
LCD_G3: J15.23(G4) R177.2
LCD_G4: J15.24(G3) R181.2
LCD_G5: J15.25(G2) R178.2
LCD_G6: J15.26(G1) R182.2
LCD_G7: J15.27(G0) R180.2
LCD_HSYNC: J15.11(HS) R151.2
LCD_PCLK: J15.37(DCLK) R150.2
LCD_R0: J15.12(B7) R171.2
LCD_R1: J15.13(B6) R169.2
LCD_R2: J15.14(B5) R173.2
LCD_R3: J15.15(B4) R170.2
LCD_R4: J15.16(B3) R204.2
LCD_R5: J15.17(B2) R202.2
LCD_R6: J15.18(B1) R175.2
LCD_R7: J15.19(B0) R172.2
LCD_VDDA: C785.1 D5.1 J15.43(AVDD) Q12.3(DRAIN) R216.1
LCD_VSYNC: J15.10(VS) R152.2
LED0/PHYAD0: R38.1 R40.2 U66.11(LED0/PHY_AD0)
LED3: R34.1 R51.1 U66.12(LED3)
MDI_RN: D14.1(ANODE) T4.8(RD-) U66.26(MDI_RN)
MDI_RP: D14.2(CATHODE) T4.6(RD+) U66.27(MDI_RP)
MDI_TN: D13.1(ANODE) T4.3(TD-) U66.29(MDI_TN)
MDI_TP: D13.2(CATHODE) T4.1(TD+) U66.30(MDI_TP)
MIC_BIAS_0: C200.1 C201.1 R120.2 R121.1 R122.1
MIC_IN: CON23.1 D17.1(ANODE) R554.2
MIPI_RESETB: C16.2 J15.44(RESET) R219.2
MODE: J15.8(MODE) R574.2 R575.2
PAD_GPIO85: TP60.1 U41.5(GPIO85)
PAD_TTL0: R171.1 U41.56(TTL0)
PAD_TTL1: R169.1 U41.57(TTL1)
PAD_TTL2: R173.1 U41.58(TTL2)
PAD_TTL3: R170.1 U41.59(TTL3)
PAD_TTL4: R204.1 U41.60(TTL4)
PAD_TTL5: R202.1 U41.61(TTL5)
PAD_TTL6: R175.1 U41.65(TTL6(MIPI_TX_D0P))
PAD_TTL7: R172.1 U41.66(TTL7(MIPI_TX_D0N))
PAD_TTL8: R176.1 U41.67(TTL8(MIPI_TX_D1P))
PAD_TTL9: R174.1 U41.68(TTL9(MIPI_TX_D1N))
PAD_TTL10: R179.1 U41.69(TTL10(MIPI_TX_CKP))
PAD_TTL11: R177.1 U41.70(TTL11(MIPI_TX_CKN))
PAD_TTL12: R181.1 U41.71(TTL12(MIPI_TX_D2P))
PAD_TTL13: R178.1 U41.72(TTL13(MIPI_TX_D2N))
PAD_TTL14: R182.1 U41.73(TTL14(MIPI_TX_D3P))
PAD_TTL15: R180.1 U41.74(TTL15(MIPI_TX_D3N))
PAD_TTL16: R186.1 R710.1 U41.79(TTL16)
PAD_TTL17: R196.1 R708.1 U41.80(TTL17)
PAD_TTL18: R199.1 R713.1 U41.81(TTL18)
PAD_TTL19: R197.1 R711.1 U41.82(TTL19)
PAD_TTL20: R201.1 R715.1 U41.83(TTL20)
PAD_TTL21: R198.1 R712.1 U41.84(TTL21)
PAD_TTL22: R203.1 R717.1 U41.85(TTL22)
PAD_TTL23: R200.1 R714.1 U41.86(TTL23)
PAD_TTL24: R150.1 R718.1 U41.87(TTL24)
PAD_TTL25: R151.1 R716.1 U41.88(TTL25)
PAD_TTL26: R152.1 U41.89(TTL26)
PAD_TTL27: R153.1 U41.90(TTL27)
PM_IRIN: R43.1 U41.32(PM_IRIN)
PM_LED0: R577.1 U41.103(PM_LED0)
PM_LED1: R578.1 U41.104(PM_LED1)
PM_RESET: C116.2 R22.1 U41.33(PM_RESET)
PM_SD20_CDZ: R147.2 U41.91(SD_CDZ)
PM_SPI_CLK: R23.1 R24.1 U14.6(SCLK) U41.27(PM_SPI_CK)
PM_SPI_CZ: R106.2 U14.1(CS#) U41.26(PM_SPI_CZ)
PM_SPI_DI: R25.1 R26.1 U14.5(SI/SIO0) U41.28(PM_SPI_DI(MOSI))
PM_SPI_DO: U14.2(SO/SIO1) U41.29(PM_SPI_DO(MISO))
PM_SPI_HLD: R71.1 U14.7(NC/SIO3) U41.30(PM_SPI_HLD)
PM_SPI_WPZ: R27.1 R28.1 U14.3(WP#/SIO2) U41.31(PM_SPI_WPZ)
PM_UART_RX: R30.1 U41.34(PM_UART_RX)
PM_UART_RX_1: CON3.3 R30.2
PM_UART_TX: R29.1 U41.35(PM_UART_TX)
PM_UART_TX_1: CON3.4 R29.2
PM_VID1: Q15.1(GATE) R76.2 R238.1 R580.1
PNL_PWRCTL: R111.2 U4.4(~{SHDN}) U41.122(GPIO5(PWM1))
Power_12V: K2.3 K2.4 R54.2
PWR_KEY: Q16.3(DRAIN) R62.2 U41.6(GPIO86)
REGOUT: R57.2 U66.28(REGOUT)
RMII_COL: R41.1 U66.4(COL/RMII)
RMII_MDC: R708.2 U66.22(MDC)
RMII_MDIO: R35.1 R710.2 U66.23(MDIO)
RMII_REF_CLK: R37.1 R712.2
RMII_RST: C797.1 R55.2 R716.2 U66.32(RESET_N)
RMII_RX_D0: R711.2 U66.18(RXD0)
RMII_RX_D1: R715.2 U66.17(RXD1)
RMII_RX_DV: R10.1 R713.2 U66.19(RXDV/TPN_FIBER)
RMII_TX_D0: R717.2 U66.9(TXD0)
RMII_TX_D1: R714.2 U66.8(TXD1)
RMII_TX_EN: R718.2 U66.5(TXEN)
RTC_IN: C120.1 U41.18(XTAL_IN_32K) Y2.1
RTC_OUT: C121.1 U41.19(XTAL_OUT_32K) Y2.2
SAR_GPIO0: R821.1 TP61.1 U41.22(SAR_GPIO0)
SAR_GPIO1: R238.2 U41.21(SAR_GPIO1)
SAR_GPIO2: CON25.1 R822.1 R833.2 U41.20(SAR_GPIO2)
SD1_CDZ: R14.1 R147.1 SD1.9(CD) U68.3(IO_2)
SD1_CLK: R141.1 SD1.5(CLK) U67.3(IO_2)
SD1_CMD: R143.1 SD1.3(CMD) U67.1(IO)
SD1_D0: R142.1 SD1.7(DAT0) U68.4(IO_3)
SD1_D1: R144.1 SD1.8(DAT1) U68.6(IO_4)
SD1_D2: R145.1 SD1.1(DAT2) U67.6(IO_4)
SD1_D3: R146.1 SD1.2(CD/DAT3) U67.4(IO_3)
SD_3.3V: C587.1 C590.1 Q3.3(DRAIN) R13.1 SD1.4(VDO)
SD_CLK: R141.2 U41.94(SD_CLK)
SD_CMD: R143.2 U41.95(SD_CMD)
SD_D0: R142.2 U41.93(SD_D0)
SD_D1: R144.2 U41.92(SD_D1)
SD_D2: R145.2 U41.97(SD_D2)
SD_D3: R146.2 U41.96(SD_D3)
SDIO_EN: C587.2 Q3.1(GATE) R12.1 U41.99(GPIO0)
SE_XTAL_OUT: C805.2 U41.16(SE_XTAL_OUT)
SP+: CON22.2 D18.2 U64.8(VOUT2)
SP-: CON22.1 D18.1 R101.2 U64.5(VOUT1)
SPI_CLK: JP4.3 LED11.2 U41.126(GPIO9_UART2_TX(SPI0_CK))
SPI_CS: JP4.2 LED12.2 U41.125(GPIO8_UART2_RX(SPI0_CZ))
SPI_DI: JP4.4 LED10.2 U41.127(GPIO10(SPI0_DI))
SPI_DO: JP4.5 LED9.2 U41.128(GPIO11(SPI0_DO))
Sys_PWR_EN: R72.2 U41.10(GPIO90)
TP_INT: CON2.4 U41.2(GPIO13) U69.4(IO_3)
TP_RTS: C709.1 CON2.3 R218.2 U41.100(GPIO1) U69.6(IO_4)
TP_SCL: CON2.2 R217.2 U41.101(GPIO2(I2C1_SCL)) U69.1(IO)
TP_SDA: CON2.1 R6.2 U41.102(GPIO3(I2C1_SDA)) U69.3(IO_2)
TRX_OUT: C728.1 L96.2 R559.1 U10.6(ANT)
UART1_RX: JP2.2 R547.2 U41.38(UART1_RX)
UART1_TX: JP2.3 R546.2 U41.39(UART1_TX)
UART_RX: TP12.1(TP) U11.16(UART1_RX)
UART_TX: TP52.1(TP) U11.15(UART1_TX)
VCOM: C635.1 J15.6(VCOM) J15.46(VCOM) VCOM.1(\) VR2.2(WIPER)
VGH: C783.1 D22.2(CATHODE) J15.41(VGH) R52.1 R108.2
VGL: C782.1 D21.1(ANODE) J15.42(VGL) R81.1 R215.2
WIFI_ANT: J4.1(RFIN) L96.1 L97.2 VR1.2
WIFI_CLK: C716.1 R834.2 U11.27(XTAL_P) Y3.3(Xout)
WIFI_EN: R240.1 U41.3(GPIO14)
WIFI_PWR_EN: C803.2 Q17.1(GATE) R832.1 R833.1
WIFI_RST: C181.1 R17.2 R240.2 U11.17(RESETN)
X1_INPUT: C252.1 U66.2(X1) Y4.1
X2_OUTPUT: C251.1 U66.3(X2) Y4.2
XTAL_IN: C119.1 U41.14(XTAL_IN) Y1.1(Xin)
XTAL_OUT: C118.1 U41.15(XTAL_OUT) Y1.3(Xout)
N22294655: C202.1 C203.1 R122.2 R124.1 R554.1
N27254527: R824.2 U64.1(~{STANDBT})
N28073323: C749.2 R103.1 R205.1
N28082669: L94.1 U3.3(Vout)
N28082762: R4.2 R5.2 U3.5(FB)
N28083855: L2.1 U2.3(Vout)
N28083953: R2.2 R3.2 R107.2 U2.5(FB)
N28147299: C659.1 D2.1 R215.1
N28147349: C263.1 C621.1 C628.1 D3.1(A) L35.2 U4.1(SW)
N28147363: C621.2 D2.3
N28147408: C676.1 D2.2 D6.1
N28147466: C624.2 C625.1 C784.1 D3.2(C) Q12.2(SOURCE) R109.1
N28147514: C624.1 R109.2 R110.1 U4.3(FB)
N28147542: C628.2 D6.3
N28147655: C627.1 D5.2 R108.1
N28147689: C263.2 D5.3
N28160133: C717.1 U11.26(XTAL_N) Y3.1(Xin)
N28160414: R556.2 U11.2(GPIO23)
N28160468: R557.2 U11.3(GPIO22)
N28160512: TP15.1(TP) U11.4(GPIO21)
N28160549: TP14.1(TP) U11.5(GPIO20)
N28160582: C114.2 U11.6(CVDDCAP)
N28160598: R223.2 U11.7(CLK_SEL)
N28160697: R21.2 U11.13(RREF)
N28168377: R231.2 U55.3(PG)
N28168381: C732.1 U55.7(BST)
N28168385: C732.2 L5.1 U55.6(LX)
N28168436: C733.1 R183.1 R232.1 U55.2(FB)
N28169331: LED1.1 R1.2
N28170584: L8.1 U8.3(LX)
N28170641: C665.1 R234.2 U8.1(EN)
N28170676: C743.2 R19.1 R235.2 R236.2 U8.6(FB)
N28170899: Q15.3(DRAIN) R235.1
N28360076: C794.1 R99.1 U64.6(VCC)
N28360113: C747.1 U64.2(BYPASS) U64.3(VIN+)
N28360138: R101.1 R103.2 U64.4(VIN-)
N28371199: R576.1 U8.5(PG)
N28376830: C148.1 T1.2(TCT)
N28376844: D16.1(A) R59.1 T1.10(TCM-) T1.15(TCM)
N28376861: C149.1 T1.7(RCT)
N28377016: C152.1 R59.2
N28382132: D4.1(A) L4.2 U6.1(SW)
N28532611: R588.1 U65.7(B)
N28532614: R589.1 U65.6(A)
N28536866: JP9.2 R593.2
N28536921: D10.1(A1) Q16.1(GATE) R54.1 R63.2
N28537267: D10.2(A2) R72.1
N28703686: C253.1 C254.1 R57.1
N28704303: CON7.1(A+) T4.16(TX+)
N28704360: CON7.2(A-) T4.14(TX-)
N28704372: C160.1 T4.2(TCT)
N28704379: CON7.3(B+) T4.11(RX+)
N28704413: D15.1(A) R56.1 T4.10(TCM-) T4.15(TCM)
N28704441: CON7.6(B-) T4.9(RX-)
N28704453: C161.1 T4.7(RCT)
N28704562: CON7.11(ORG+) R34.2
N28704627: C157.1 R56.2
N28732399: LED9.1 R825.2
N28732553: LED10.1 R826.2
N28732679: LED11.1 R827.2
N28732717: LED12.1 R828.2
N28761735: R39.1 U66.25(ISET)
N28767929: CON7.10(GRN-) R40.1
N28917651: C729.1 L97.1
N28918056: R214.1 VR2.1(A)
N28918057: R212.2 VR2.3(B)
N28919988: C737.1 U55.4(SS)
N28920245: CON7.9(GRN+) R830.2
N28938810: C805.1 R834.1

Not connected (* = marked no-connect by the designer): CON3 1*; CON7 4(C+)* 5(C-)* 7(D+)* 8(D-)*; CON21 4(C+) 5(C-) 7(D+) 8(D-); J11 1* 2* 3* 8*; J15 45(NC)*; Logo 1(TP)*; T1 4(NC1)* 5(NC2)* 12(NC3)* 13(NC4)*; T4 4(NC1)* 5(NC2)* 12(NC3)* 13(NC4)*; U1 4(FB)*; U11 1(ATB) 14(GPIO4) 18(TEST_MODE)* 19(PWR_ON)*; U45 1(IO) 5(VCC) 6(IO_4); U66 1(TXER/FXSD)* 6(TXD3)* 7(TXD2)* 15(RXD3)* 16(RXD2)* 24(TEST_ON)*; U67 5(VCC); U68 1(IO) 5(VCC); U69 5(VCC)

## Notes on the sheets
sheet 1
- ICC < 200mA
- As close to IP101GR
  Pin31 as possible
- As close to IP101GR
  Pin13 as possible
- 50MHz CLOCK OUT
  Generate by IP101A
- LED and PHY address
  Configuration
- As close to IP101GR
  Pin28 as possible
- This schematic sets PHY address to
  00001b.
- use 25M crystal
- Low Active
- 1. Do not let these PHY address pins floating for the
  latched-in settings after the power is ready.
- CRYSTAL
  as close as to chip
- Set IP101A
  to RMII Mode
- Pull high
- Pull down
- COL/RMII
- RMII mode
- MII mode
- CRS
- LED mode2
- LED mode1
- RX_DV
- Fiber mode
- TP mode
- LED_PM[1]  Active when linked in 100Base-TX
  and blinking when transmitting or receiving
  LED_PM[0] Active when linked.
- 2. Notes: Mount 33 ohm resistor for ESD and as close to
  chip  as possible.
sheet 2
- Revision
- REV
- DESCRIPTION
- DATE
- APPROVED
- S01A
- Init
- First Release
- 1  Add ESD Protect
- 2  Add Q17 PMOS WIFI Power Control
- 3  Add SSD201 GPIO Control WIFI Reset ,remove SSW101B 19 Pin ,NC
- 4  SSD201 output 24M Clcok add AC couple and RC Circuit
- 5  Pin36/36 UART Function Change to GPIO
- 6  Add  VGH/VGL D21/D22  Zener diode   ---------20200701
sheet 3
- SSD201
- FUART
- FUART
- FUART
- MIC
- MIC
- Microphone
- UART
- UART
- UART
- Audio out
- Audio out
- Audio
- Audio Amp.
- Speaker
- RTC crystal
- 32.768KHz
- RTC_CLK
- Status LED
- 24MHz
- XTAL_CLK
- GPIO
- LED
- 24MHz crystal
- DDR2  512Mbit
  1333M
- UART0
- Debug port
- Data
- IR in
- GPIO
- GPIO
- Infrared LED
- IRin
- Reset
- SPI
- Reset
- RC Reset
- Nor flash
- SPI
- PWM
- PWM
- PWM
- I2C
- I2C
- I2C
- SPI
- SPI
- SPI
- 0.9V
- 1.8V
- TTL/MIPI/RMII
- TTL/MIPI/RMII
- TTL/MIPI/RMII
- 3.3V
- SDIO 2.0
- Sd card slot
- SDIO 2.0
- Power tree
- 5V
- 3.3V
  NORMAL
- 12V
- FR9855
- TMI3408
- TMI3408
- VDD_1V8
- TMI3408
- 1V8_Normal_0
- TMI3253S
- 1V0_Normal
    (0.9V)
sheet 4
- DC 12V Input
- +5V Power
- 5V DC-DC
- Power
- R1
- R2
- Vout=0.765x(1+R1/R2)
- LDO 1V8 MIPI Panel
- 200mA ?
- DC 3V3 PWR
- DDR2 1V8
- FB=0.6V
- DC 1V0   Core  Power
- DC 1V8 DDRII PWR (Internal)
- DDR2 1V8
- Close to Main Chip
- FB=0.6V
- R1
- Vout=0.6 x(1+R1/R2)
- 2
- S
- 1
- G
- 100//300K = 1.8V
  100K = 1.5V
- 3
- D
- R2
- 2N7002
- Vout = 0.6* (1+150K/100K) = 1.5V
- VID_1
- R235//R236
- 1V0_STD
- L
- 100K
- 0.903V
- H
- 100K//300K
- 1.005V
- Both side
- Interrupt
- Pull Down
- System Standby
- Power On Ckt
- Power KEY
- NMOS
sheet 5
- RESET
- Debug UART
- RTC PWR
- IR Receiver
- AVDD_RTC Current <3uA @25°
- High Active
- AUDIO
- Series Resistance TTL ESD Protect
- AMIC/DMIC Work
  Only option one
- BOOT STRAPPING
- (DEFAULT)
- Pull Down
- M[0]
- PD
- (DEFAULT)
- Pull UP
- M[1]
- PU
- (DEFAULT)
- Pull UP
- M[2]
- PU
- Chip Config. [2:0]
- Low
- High
- [0], PM_SPI_CLK
- NOR
- NAND
- [1], PM_SPI_DI
- NO
- [2], PM_SPI_WPZ_BOOT
- ROM
- SW Development
  24310
- Default Boot From SPI NAND
- SPI NAND
- System XTAL (24MHz)
- RTC XTAL (32.768KHz)
sheet 6
- Pull Down
- Power
- Must 10K
- Shutdown Current 0.1uA(Typ)
- 8ohm,1W
- SPK_SHDN
  Default : Low
  Active :High
- SMT 330nF ???
   Yes
- Line In Bias
- R554 : 6.2K
  R124 : 6.2K
  R122 : NC
  C202 :1.5nF
- Close to Main Chip
sheet 7
- VCOM
- Down Type
- 3.7V
- 10.4V
- -7V
- 16V
- Please reference HW Check
   list to TTL Swap
- I = 0.195V/R9
  130mA => R9 = 5R
- 3.3V
- 3.7V
- PCB TOP
- 2
- S
- 1
- G
- PMOS
- 3
- D
- AO3401
- VFB=1.23V;
sheet 8
- Note 1:XTAL CL
- Pull Down
- If use External clock or Oscillator,
  must connect to XTAL_P(Pin #27)
- If CL<15pF,
  C716&C717 can NC
- IF use SSD201 24M Clock，Y3 NC C717 NC
  IF use Crystal  ,  R834 NC C716 NC C717 NC
- Note 2:XTAL SPEC
- Xtal Size: 3225, 2520
  Nominal Frequency: 24
  Frequency Tolerance: ¡Ó20ppm at 25¢J¡Ó3¢J
  Frequency Stability(TC): ¡Ó10ppm at-25¢J¡ã+85¢J
  Load capacitance: 9~11pF
  Equivalent Series Resistance(ESR): < 50£[
  Shunt Capacitance(C0): ¡Ø 3pF
- CLK_SEL
  Pin #7
- GPIO22
  Pin #3
- GPIO23
  Pin #2
- Clock type
- 24MHz crystal
- NC
- float
- float
- 24MHz external
  clock or oscillator
  (default)
- low
- high
- low
- 50 Ohm RF trace
- If uses 24MHz crystal,
  let it floating
- All Caps close to IC pad.
- Don’t connect Pin#12 USB ground pin to E-PAD ground,
  this pin must connect to peripheral ground plane
- Close to Pin26 of U11
- Value
- BL-M8188FU3-B
- Part Number
- L96
- 2nH(+-0.1nH)
- SDCL1005C2N0BTDF
- 1、ON Board WIFI use WIFI_RST Pin;
  2、WIFI Daughter Board use PMOS Control WIFI Power.
- C728
- 1.0pF(+-0.1pF)
- GJM1555C1H1R0BB01
- PMOS
- L97
- 1.2nH(+-0.1nH)
- SDCL1005C1N2BTDF
- C729
- 0.5pF(+-0.1pF)
- GJM1555C1HR50BB01
- Very Important
- VR1
- NC/DCE0510D2LC
- R821/NC
- 以上物料电感顺络
  电容村田
sheet 9
- SDIO 2.0
- Series Resistance TTL ESD Protect
- PMOS
- Hi  Off
  Low On
- TFlash
- C590 and R13
  Close to SD Card
sheet 10
- R577 R578 keep away from RJ45 Connector
- LED_PM[1]  Active when linked in 100Base-TX and blinking when transmitting or receiving
  LED_PM[0] Active when linked.
- P2 - USB2.0 Host
sheet 11
- RS485
- SMT 100R ???
- TO DMIC
